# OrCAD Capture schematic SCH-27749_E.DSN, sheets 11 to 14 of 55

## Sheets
11 GVDD & OVDD Power: size C
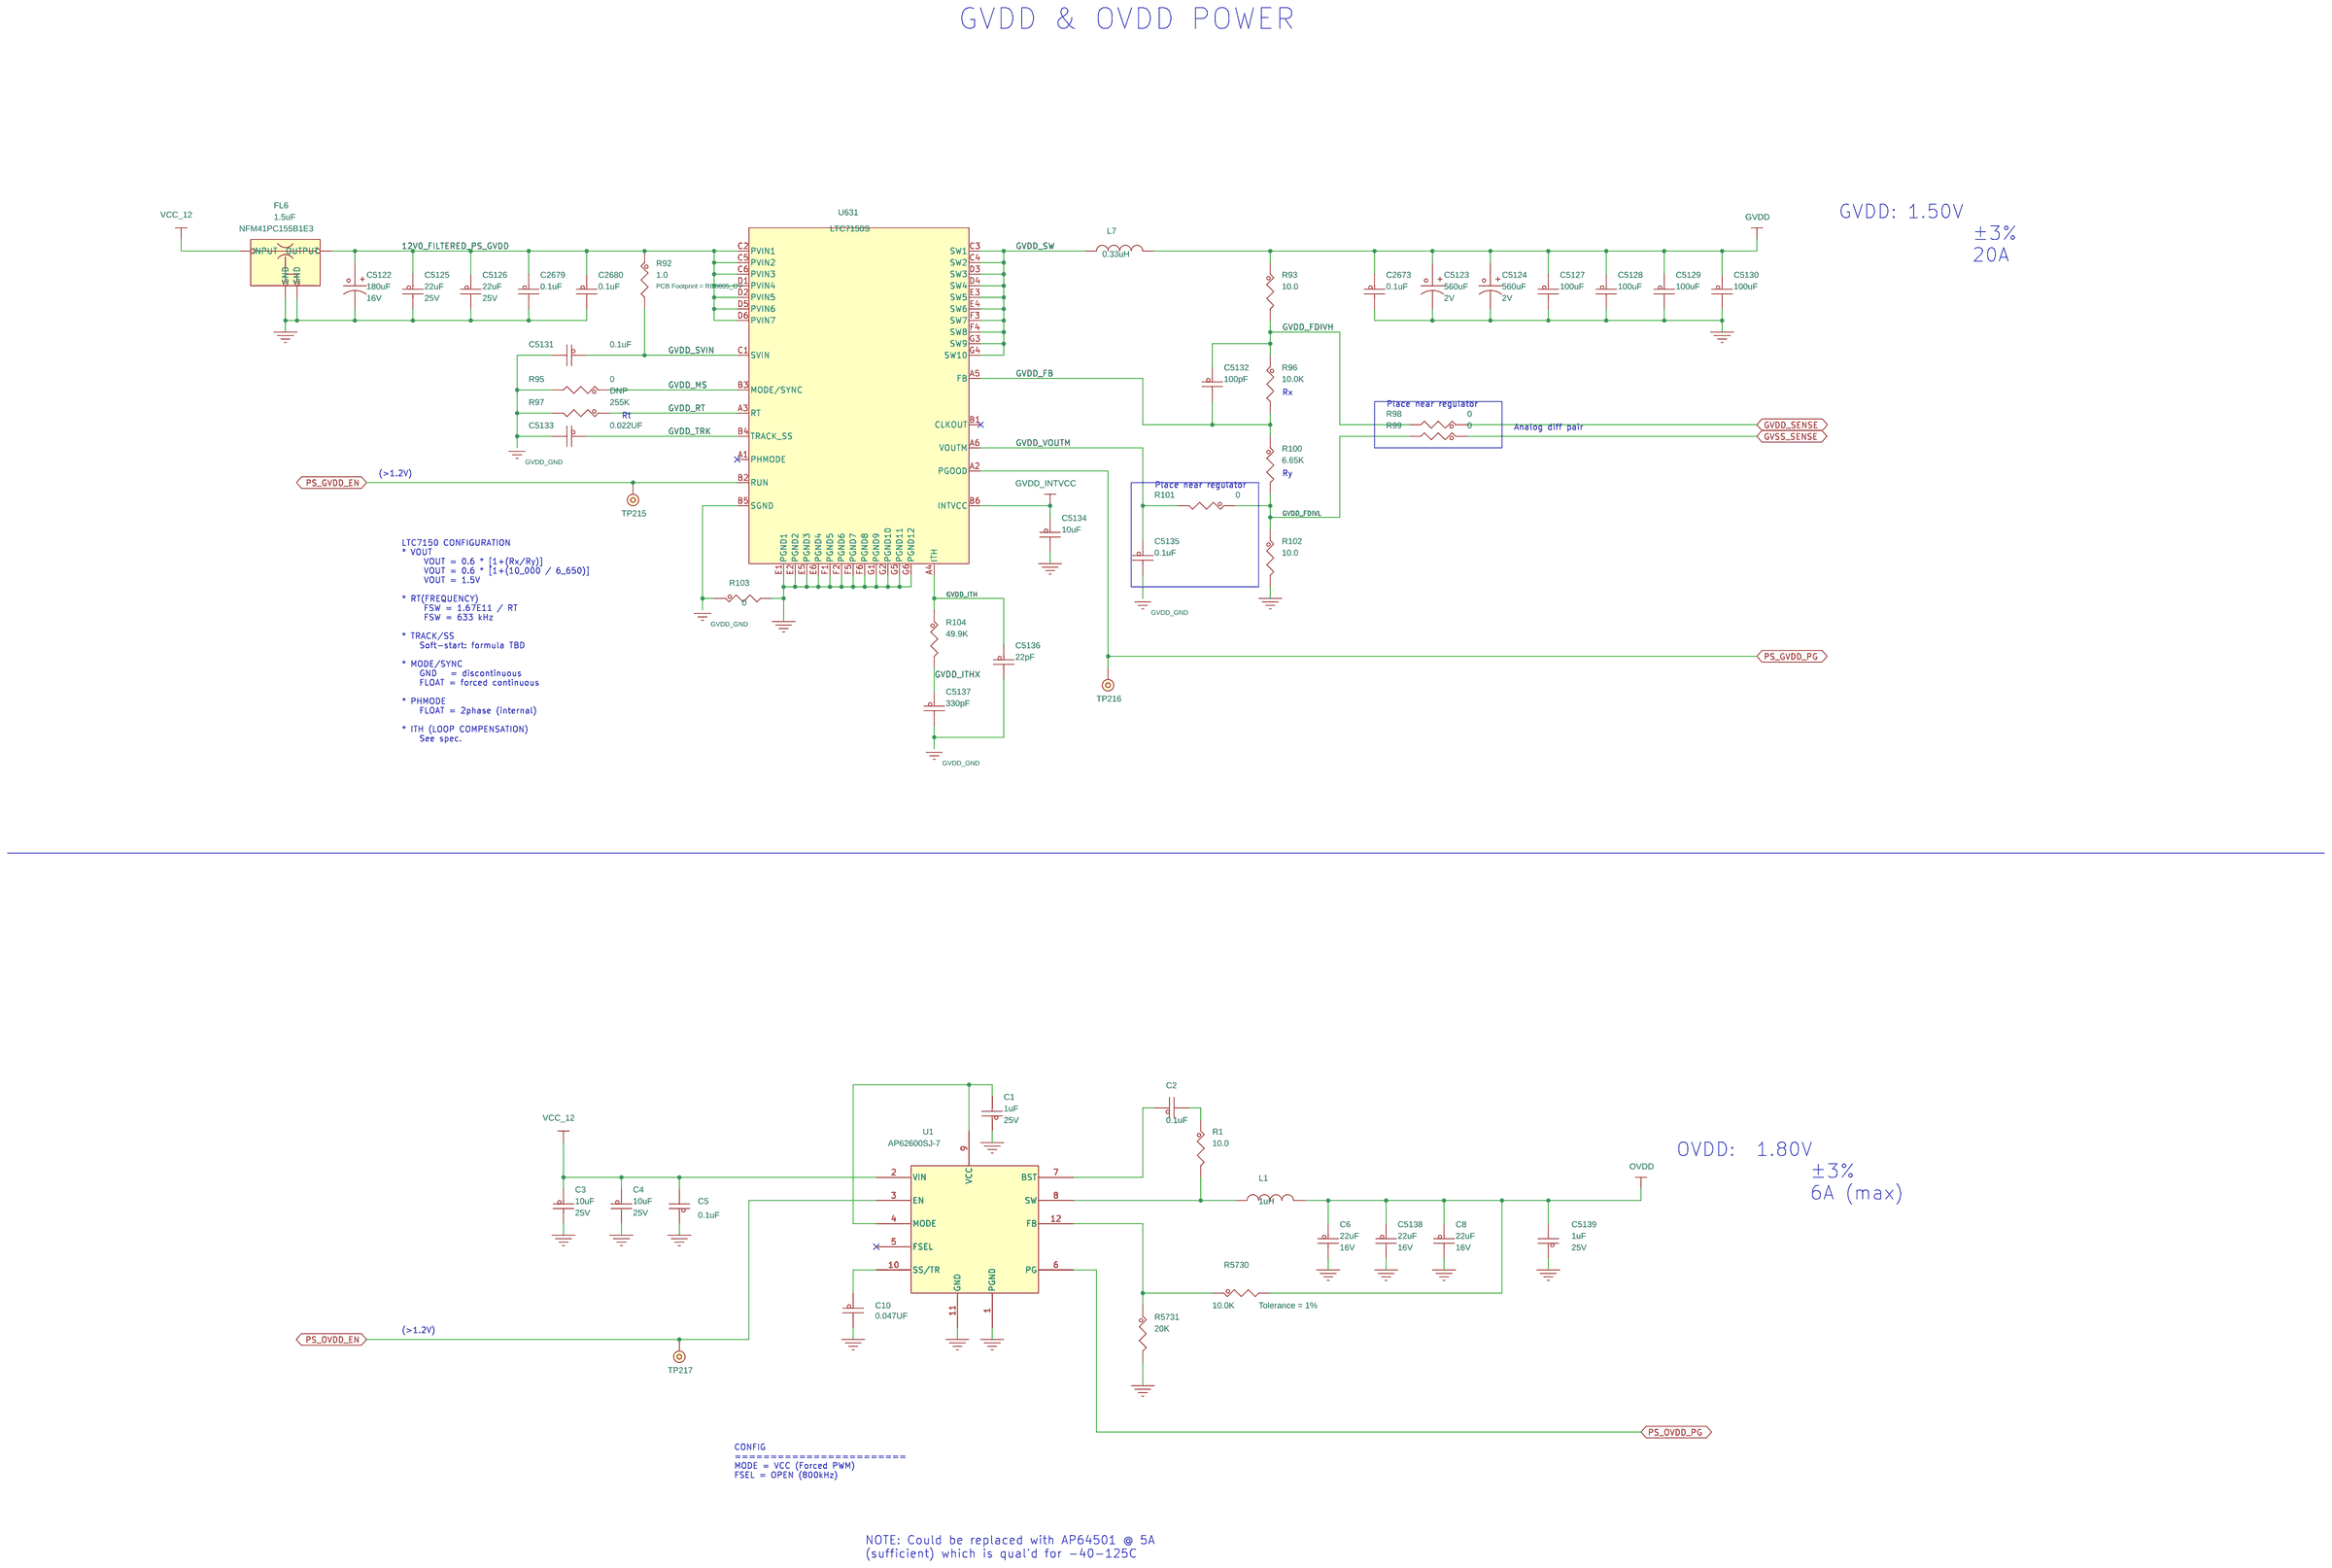
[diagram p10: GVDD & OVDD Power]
12 VDD: size C
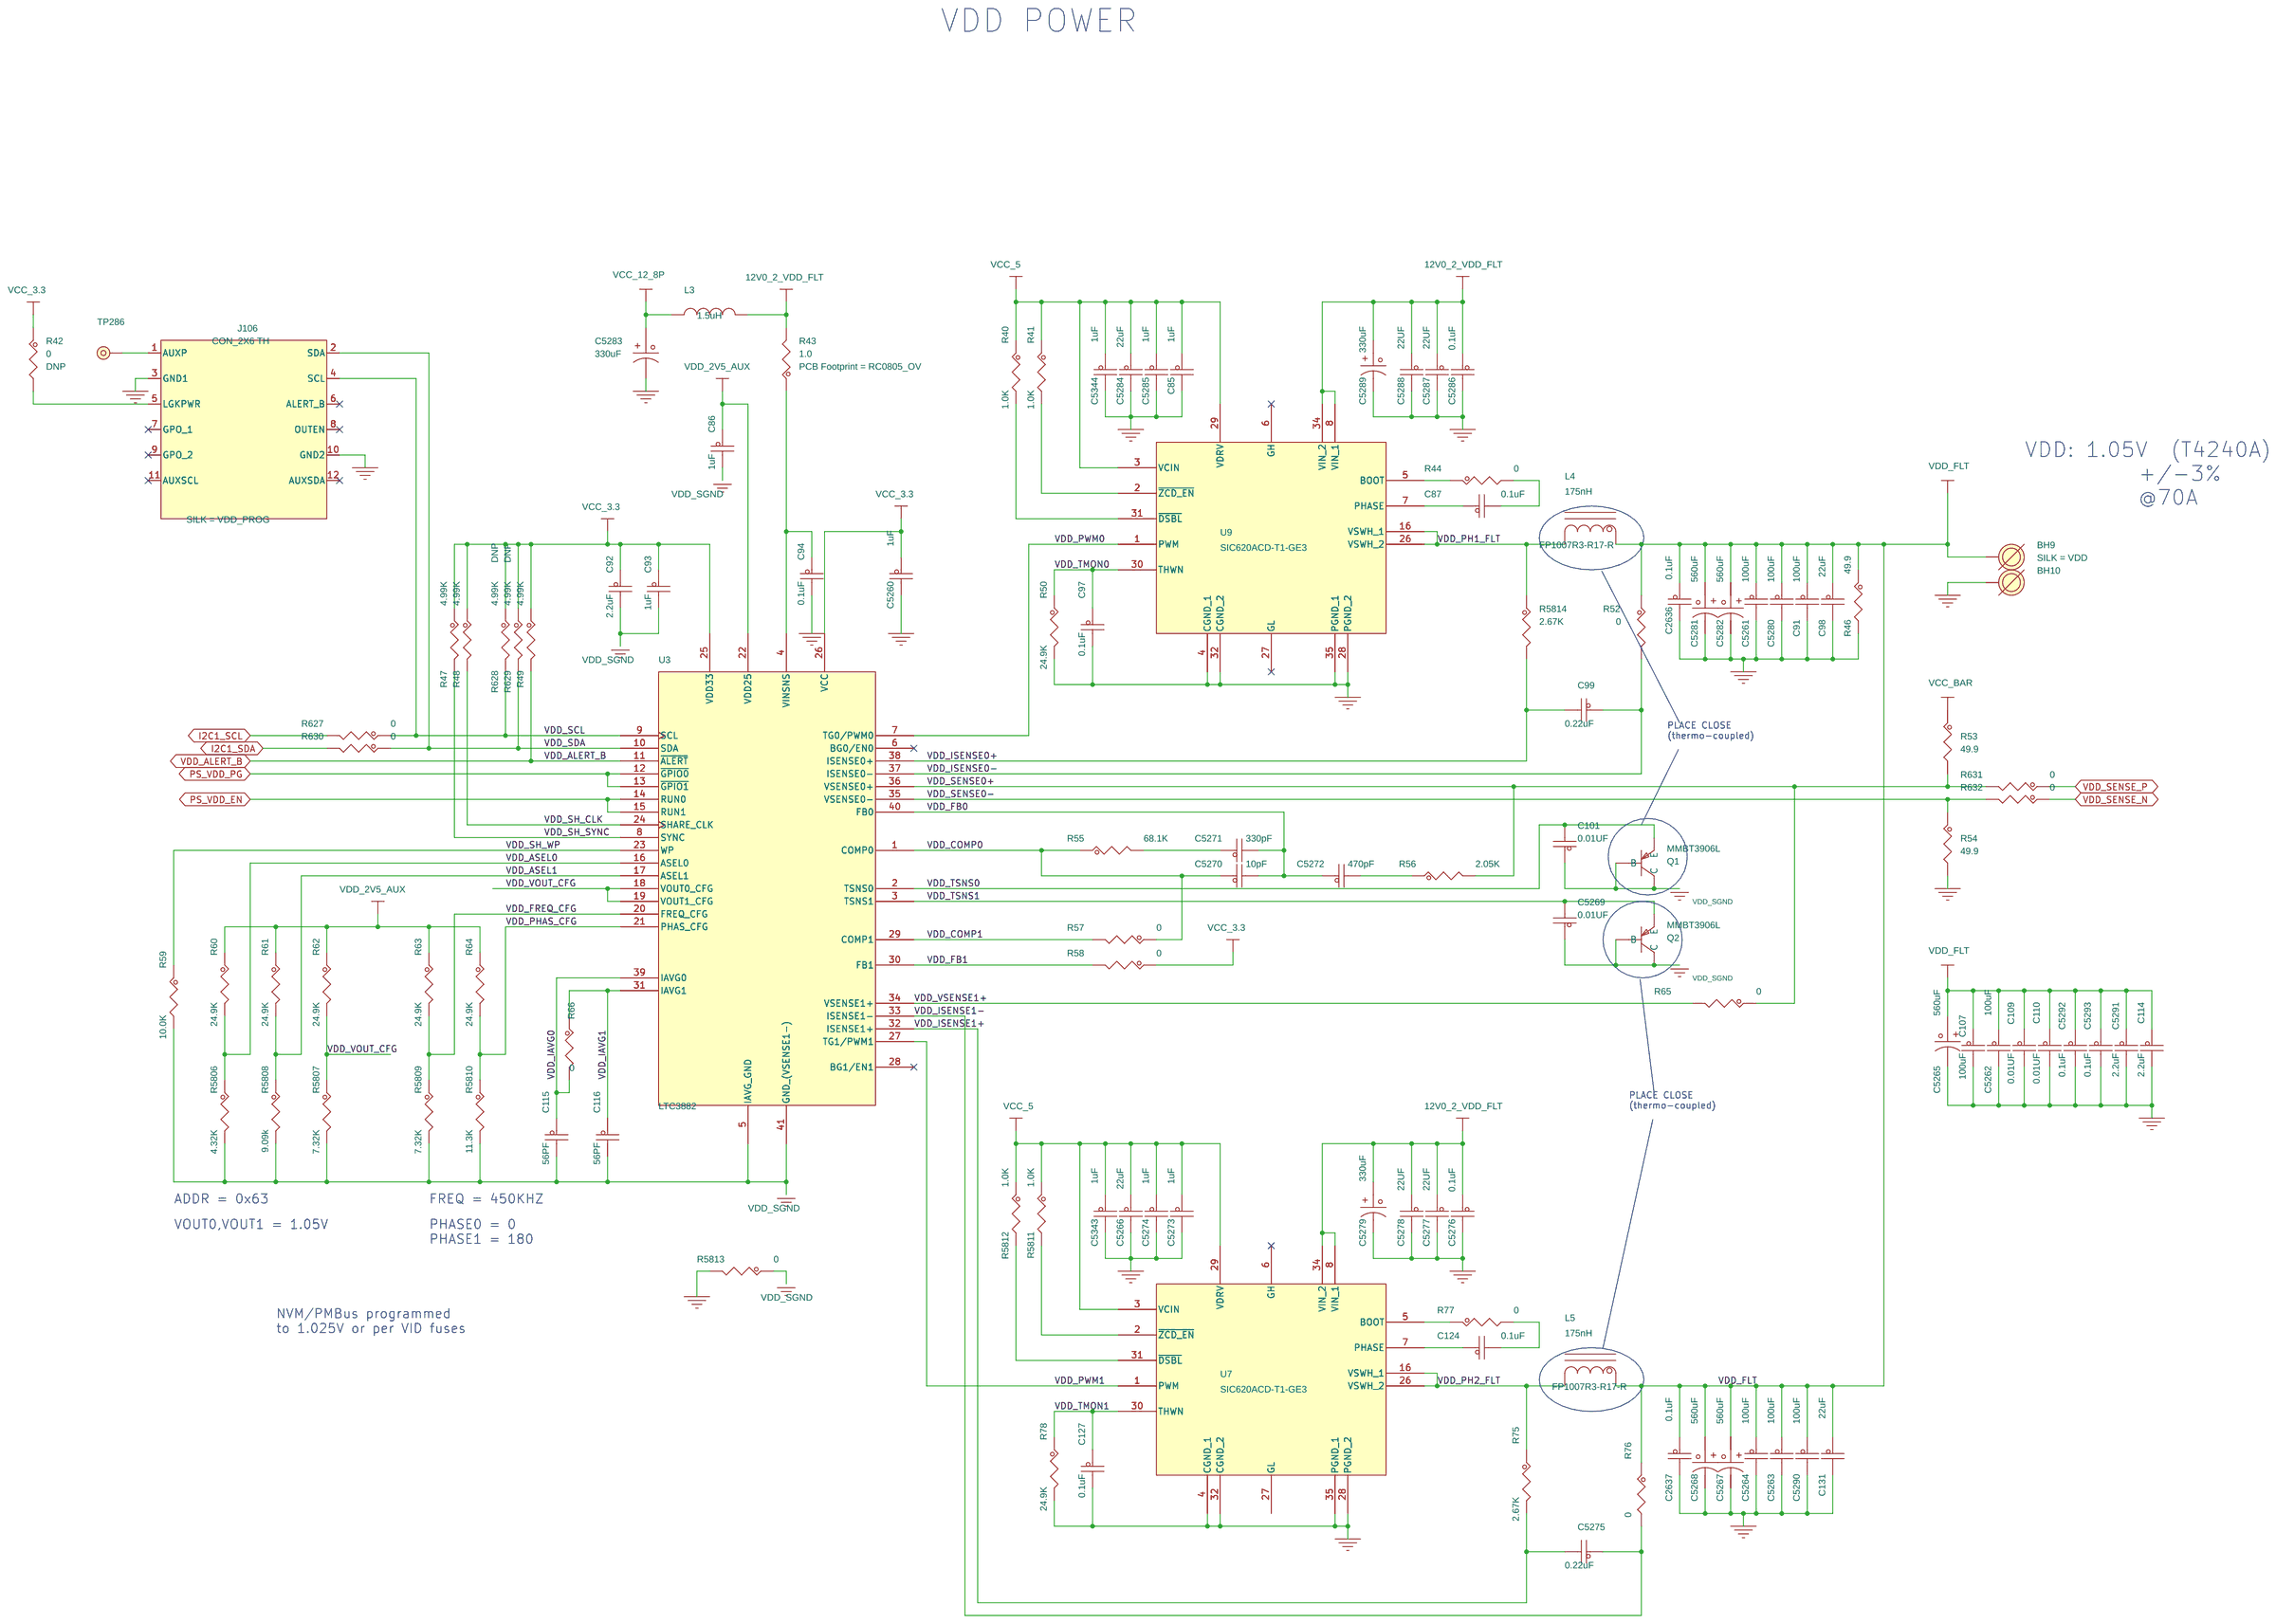
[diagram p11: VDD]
13 DDR MVREF+VTT Power: size C
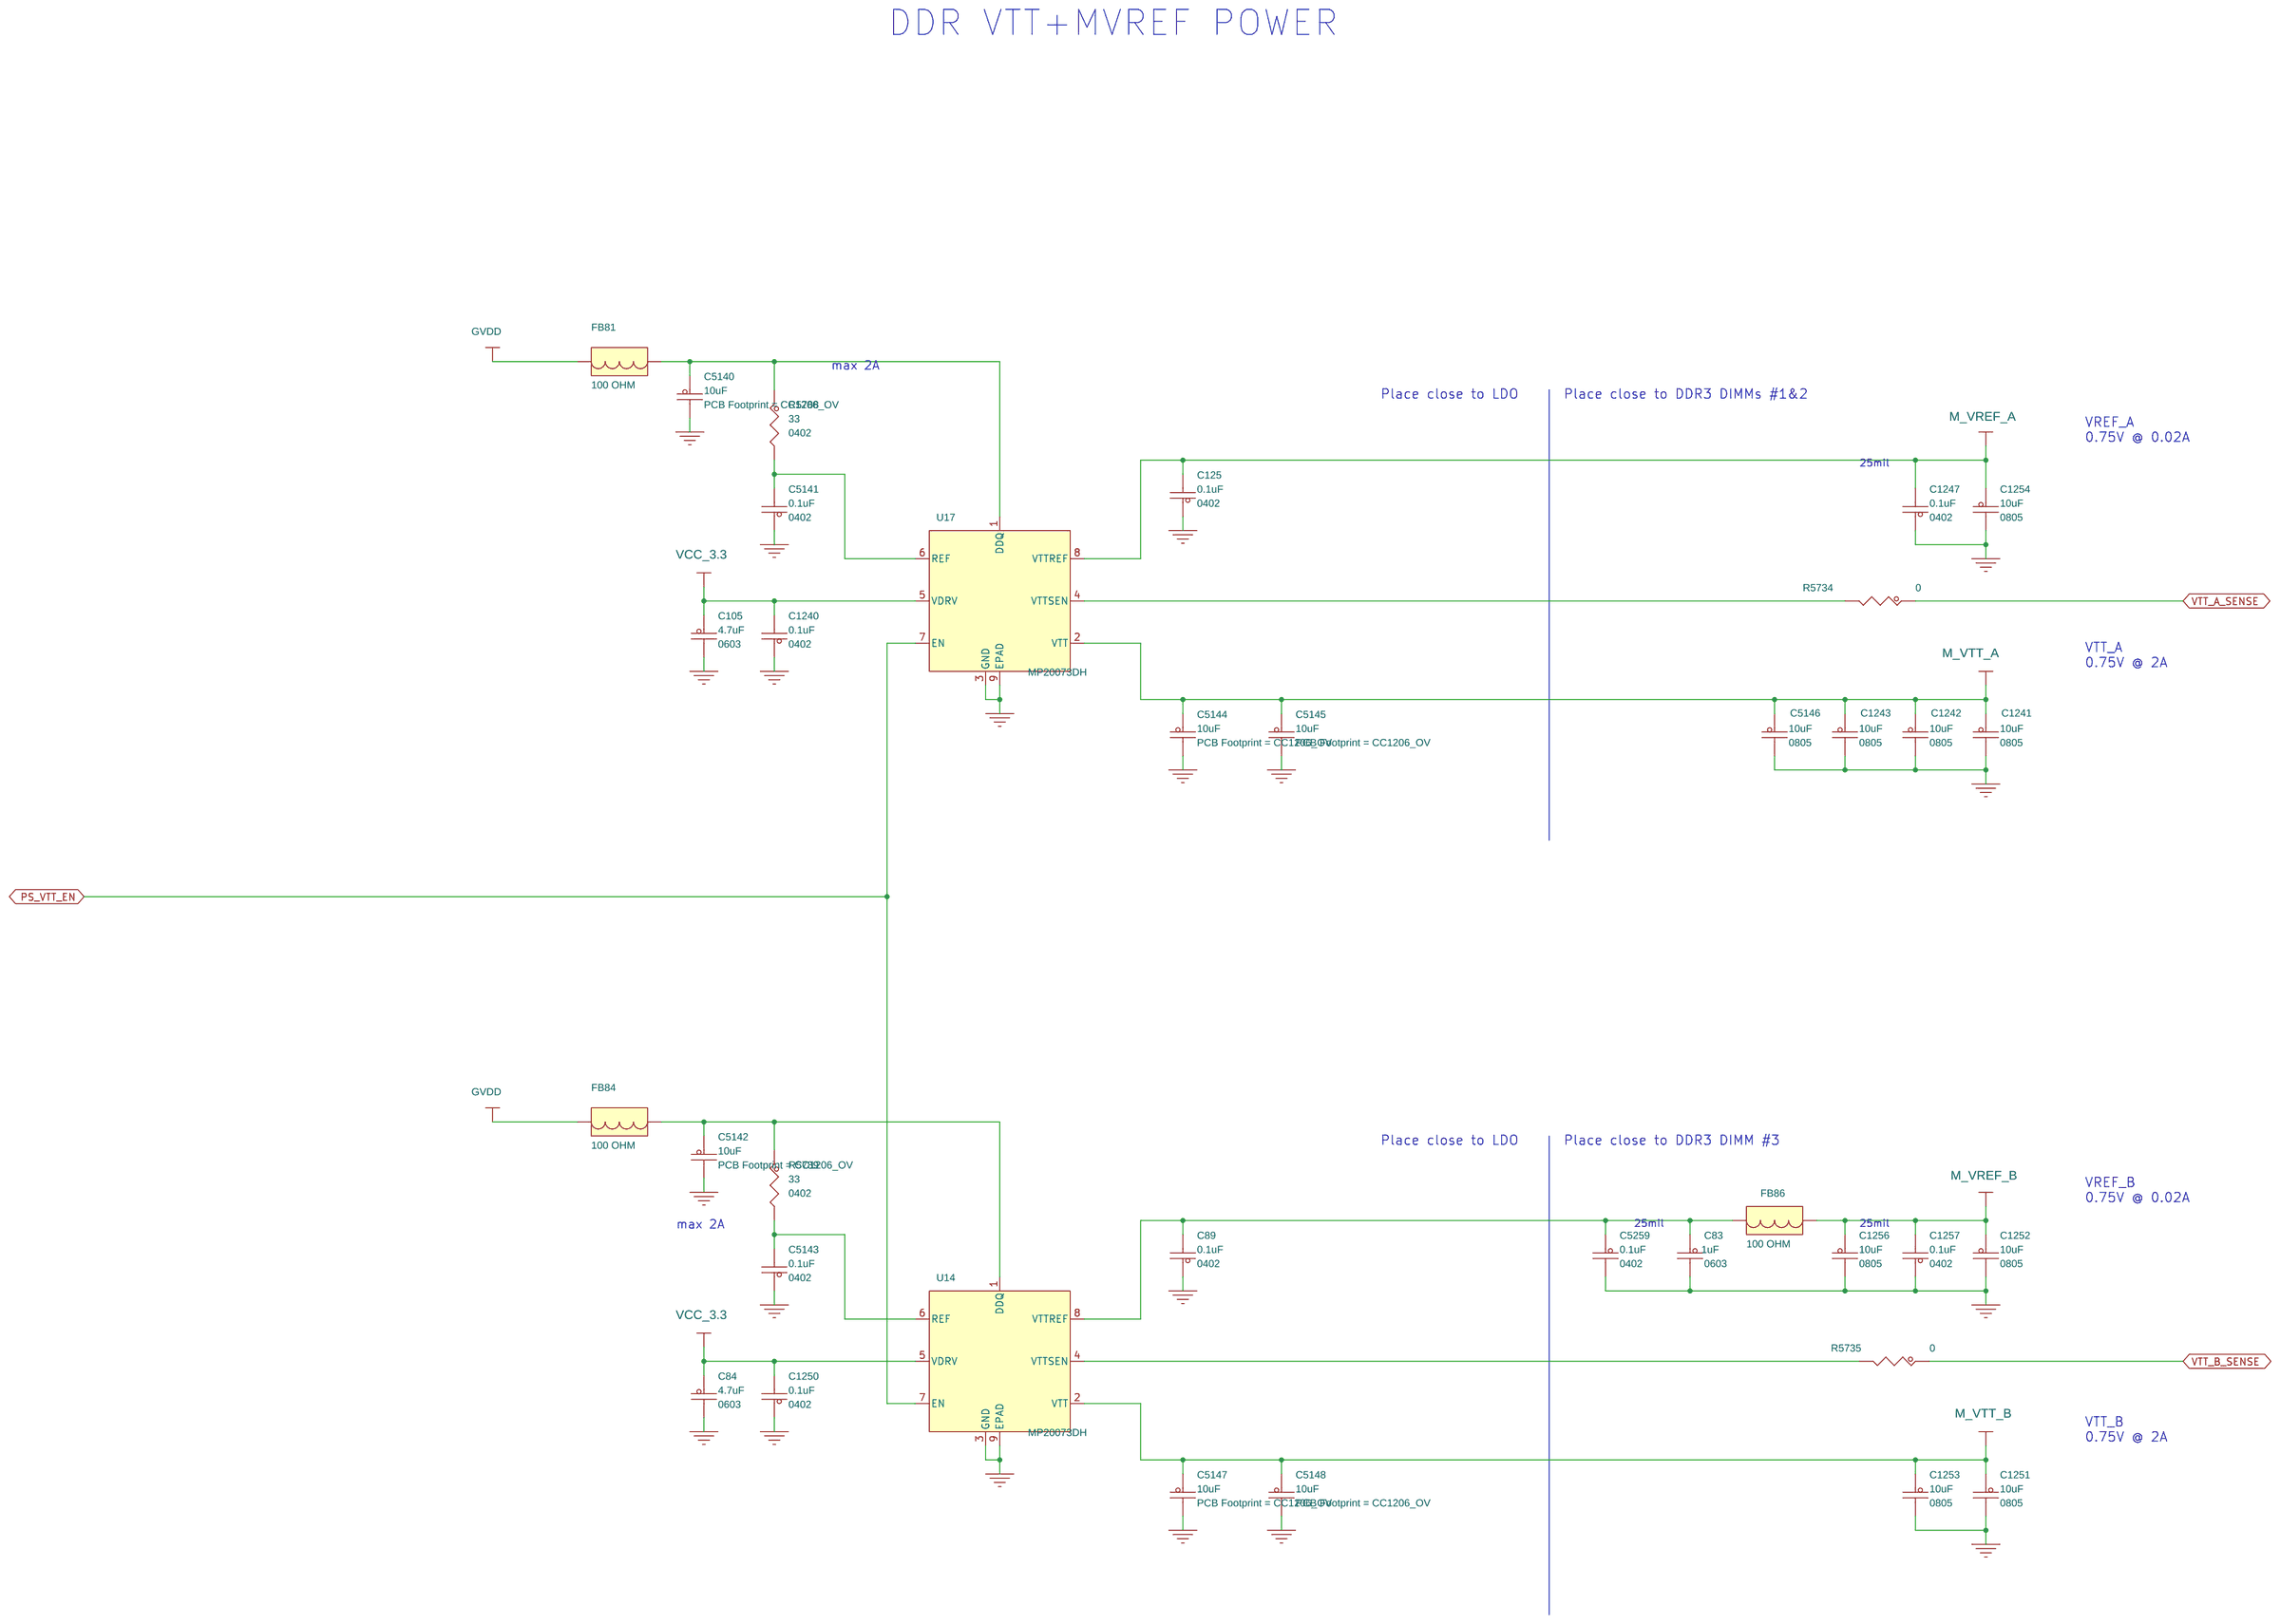
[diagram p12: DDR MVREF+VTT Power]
14 SVDD & XVDD Power: size C
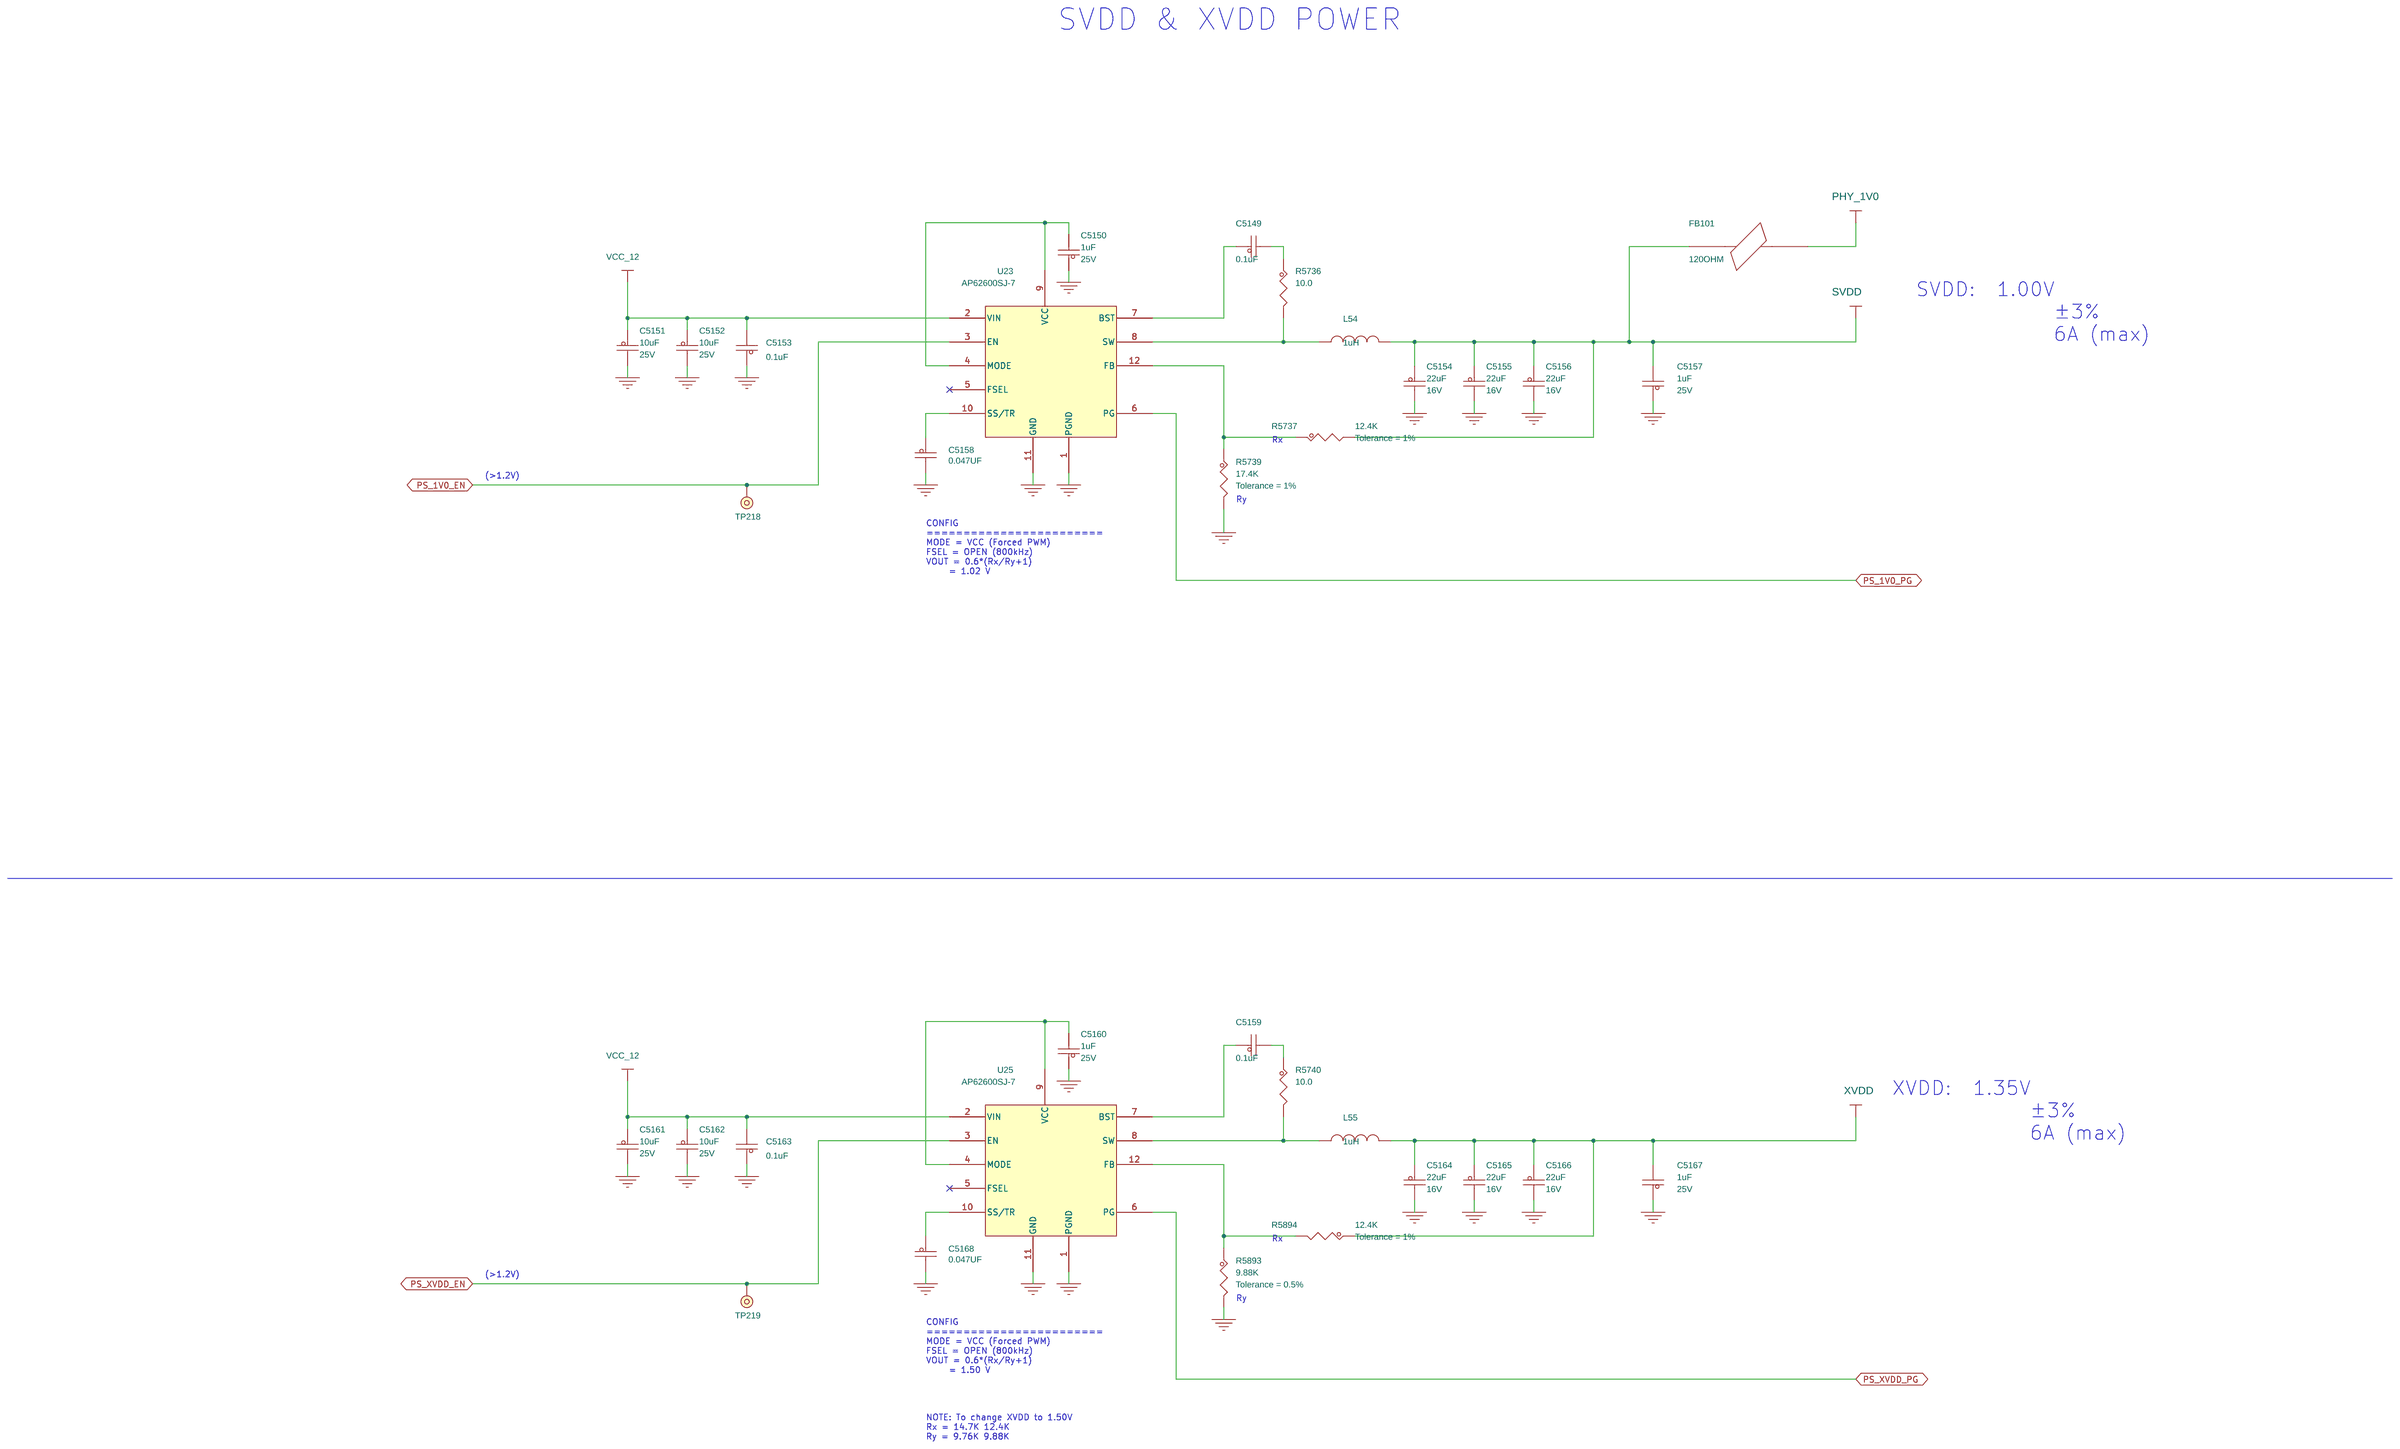
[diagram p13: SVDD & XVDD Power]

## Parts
sheet DDR MVREF+VTT Power
C83  1uF  [CC0603_OV]
C84  4.7uF  [CC0603_OV]
C89  0.1uF  [CC0402_HD]
C105  4.7uF  [CC0603_OV]
C125  0.1uF  [CC0402_HD]
C1240  0.1uF  [CC0402_HD]
C1241  10uF  [CC0603_OV]
C1242  10uF  [CC0603_OV]
C1243  10uF  [CC0603_OV]
C1247  0.1uF  [CC0402_HD]
C1250  0.1uF  [CC0402_HD]
C1251  10uF  [CC0603_OV]
C1252  10uF  [CC0603_OV]
C1253  10uF  [CC0603_OV]
C1254  10uF  [CC0603_OV]
C1256  10uF  [CC0603_OV]
C1257  0.1uF  [CC0402_HD]
C5140  10uF  [CC1206_OV]
C5141  0.1uF  [CC0402_HD]
C5142  10uF  [CC1206_OV]
C5143  0.1uF  [CC0402_HD]
C5144  10uF  [CC1206_OV]
C5145  10uF  [CC1206_OV]
C5146  10uF  [CC0603_OV]
C5147  10uF  [CC1206_OV]
C5148  10uF  [CC1206_OV]
C5259  0.1uF  [CC0402_HD]
FB81  100 OHM  [IND_0805]
FB84  100 OHM  [IND_0805]
FB86  100 OHM  [IND_0805]
R5734  0  [RC0402_25]
R5735  0  [RC0402_25]
R5788  33  [RC0402_25]
R5789  33  [RC0402_25]
U14  MP20073DH  [msop8_0p65_3p1X3p1_EPAD]
U17  MP20073DH  [msop8_0p65_3p1X3p1_EPAD]
sheet GVDD & OVDD Power
C1  1uF  [CC0603_OV]
C2  0.1uF  [CC0402_HD]
C3  10uF  [CC1206_OV]
C4  10uF  [CC1206_OV]
C5  0.1uF  [CC0402_HD]
C6  22uF  [1206_CC]
C8  22uF  [1206_CC]
C10  0.047UF  [CC0603_OV]
C2673  0.1uF  [CC0402_HD]
C2679  0.1uF  [CC0402_HD]
C2680  0.1uF  [CC0402_HD]
C5122  180uF  [cce10_3x10_3]
C5123  560uF  [cc7343a_lp]
C5124  560uF  [cc7343a_lp]
C5125  22uF  [CC0805_OV]
C5126  22uF  [CC0805_OV]
C5127  100uF  [CC1210]
C5128  100uF  [CC1210]
C5129  100uF  [CC1210]
C5130  100uF  [CC1210]
C5131  0.1uF  [CC0402_HD]
C5132  100pF  [CC0402_HD]
C5133  0.022UF  [CC0402_HD]
C5134  10uF  [CC0603_OV]
C5135  0.1uF  [CC0402_HD]
C5136  22pF  [CC0402_HD]
C5137  330pF  [CC0402_HD]
C5138  22uF  [1206_CC]
C5139  1uF  [CC0603_OV]
FL6  1.5uF  [CC_NFM41P_1806]
L1  1uH  [ind2_sq6p9_3_sm]
L7  0.33uH  [ind2_744308033]
R1  10.0  [RC0402_25]
R92  1.0  [RC0805_OV]
R93  10.0  [RC0402_25]
R95  0  [RC0402_25]
R96  10.0K  [RC0402_25]
R97  255K  [RC0402_25]
R98  0  [RC0402_25]
R99  0  [RC0402_25]
R100  6.65K  [RC0402_25]
R101  0  [RC0402_25]
R102  10.0  [RC0402_25]
R103  0  [RC0402_25]
R104  49.9K  [RC0402_25]
R5730  10.0K  [RC0402_25]
R5731  20K  [RC0402_25]
TP215  TPAD_020  [tpad_020_top]
TP216  TPAD_020  [tpad_020_top]
TP217  TPAD_020  [tpad_020_top]
U1  AP62600SJ-7  [qfn12_0p5_2p05x3p05mm]
U631  LTC7150S  [bga42_0p8_5x6]
sheet SVDD & XVDD Power
C5149  0.1uF  [CC0402_HD]
C5150  1uF  [CC0603_OV]
C5151  10uF  [CC1206_OV]
C5152  10uF  [CC1206_OV]
C5153  0.1uF  [CC0402_HD]
C5154  22uF  [1206_CC]
C5155  22uF  [1206_CC]
C5156  22uF  [1206_CC]
C5157  1uF  [CC0603_OV]
C5158  0.047UF  [CC0603_OV]
C5159  0.1uF  [CC0402_HD]
C5160  1uF  [CC0603_OV]
C5161  10uF  [CC1206_OV]
C5162  10uF  [CC1206_OV]
C5163  0.1uF  [CC0402_HD]
C5164  22uF  [1206_CC]
C5165  22uF  [1206_CC]
C5166  22uF  [1206_CC]
C5167  1uF  [CC0603_OV]
C5168  0.047UF  [CC0603_OV]
FB101  120OHM  [IND_0603]
L54  1uH  [ind2_sq6p9_3_sm]
L55  1uH  [ind2_sq6p9_3_sm]
R5736  10.0  [RC0402_25]
R5737  12.4K  [RC0402_25]
R5739  17.4K  [RC0402_25]
R5740  10.0  [RC0402_25]
R5893  9.88K  [RC0402_25]
R5894  12.4K  [RC0402_25]
TP218  TPAD_020  [tpad_020_top]
TP219  TPAD_020  [tpad_020_top]
U23  AP62600SJ-7  [qfn12_0p5_2p05x3p05mm]
U25  AP62600SJ-7  [qfn12_0p5_2p05x3p05mm]
sheet VDD
BH9  MH_180  [MH180-135P]
BH10  MH_180  [MH180-135P]
C85  1uF  [CC0402_HD]
C86  1uF  [CC0402_HD]
C87  0.1uF  [CC0402_HD]
C91  100uF  [CC1210]
C92  2.2uF  [CC0402_HD]
C93  1uF  [CC0402_HD]
C94  0.1uF  [CC0402_HD]
C97  0.1uF  [CC0402_HD]
C98  22uF  [CC0805]
C99  0.22uF  [CC0402_HD]
C101  0.01UF  [CC0402_HD]
C107  100uF  [CC1210]
C109  0.01UF  [CC0402_HD]
C110  0.01UF  [CC0402_HD]
C114  2.2uF  [CC0402_HD]
C115  56PF  [CC0402_HD]
C116  56PF  [CC0402_HD]
C124  0.1uF  [CC0402_HD]
C127  0.1uF  [CC0402_HD]
C131  22uF  [CC0805]
C2636  0.1uF  [CC0402_HD]
C2637  0.1uF  [CC0402_HD]
C5260  1uF  [CC0402_HD]
C5261  100uF  [CC1210]
C5262  100uF  [CC1210]
C5263  100uF  [CC1210]
C5264  100uF  [CC1210]
C5265  560uF  [cc7343a_lp]
C5266  22uF  [CC0805]
C5267  560uF  [cc7343a_lp]
C5268  560uF  [cc7343a_lp]
C5269  0.01UF  [CC0402_HD]
C5270  10pF  [cc0402_hd]
C5271  330pF  [CC0402_HD]
C5272  470pF  [CC0402_25]
C5273  1uF  [CC0402_HD]
C5274  1uF  [CC0402_HD]
C5275  0.22uF  [CC0402_HD]
C5276  0.1uF  [CC0402_HD]
C5277  22UF  [CC1210]
C5278  22UF  [CC1210]
C5279  330uF  [cap_10p5_rad]
C5280  100uF  [CC1210]
C5281  560uF  [cc7343a_lp]
C5282  560uF  [cc7343a_lp]
C5283  330uF  [cap_10p5_rad]
C5284  22uF  [CC0805]
C5285  1uF  [CC0402_HD]
C5286  0.1uF  [CC0402_HD]
C5287  22UF  [CC1210]
C5288  22UF  [CC1210]
C5289  330uF  [cap_10p5_rad]
C5290  100uF  [CC1210]
C5291  2.2uF  [CC0402_HD]
C5292  0.1uF  [CC0402_HD]
C5293  0.1uF  [CC0402_HD]
C5343  1uF  [CC0402_HD]
C5344  1uF  [CC0402_HD]
J106  CON_2X6 TH  [CON12_SHRD_2MM_TH]
L3  1.5uH  [IND_IHLP]
L4  175nH  [IND2_10P4X8]
L5  175nH  [IND2_10P4X8]
Q1  MMBT3906L  [SOT23]
Q2  MMBT3906L  [SOT23]
R40  1.0K  [RC0402_HD]
R41  1.0K  [RC0402_HD]
R42  0  [RC0603_OV]
R43  1.0  [RC0805_OV]
R44  0  [RC0402_25]
R46  49.9  [RC0402_25]
R47  4.99K  [RC0402_25]
R48  4.99K  [RC0402_25]
R49  4.99K  [RC0402_25]
R50  24.9K  [RC0402_25]
R52  0  [RC0402_25]
R53  49.9  [RC0402_25]
R54  49.9  [RC0402_25]
R55  68.1K  [RC0402_25]
R56  2.05K  [RC0402_25]
R57  0  [RC0402_25]
R58  0  [RC0402_25]
R59  10.0K  [RC0402_25]
R60  24.9K  [RC0402_25]
R61  24.9K  [RC0402_25]
R62  24.9K  [RC0402_25]
R63  24.9K  [RC0402_25]
R64  24.9K  [RC0402_25]
R65  0  [RC0402_25]
R66  0  [RC0402_25]
R75  2.67K  [RC0402_25]
R76  0  [RC0402_25]
R77  0  [RC0402_25]
R78  24.9K  [RC0402_25]
R627  0  [RC0402_25]
R628  4.99K  [RC0402_25]
R629  4.99K  [RC0402_25]
R630  0  [RC0402_25]
R631  0  [RC0402_25]
R632  0  [RC0402_25]
R5806  4.32K  [RC0402_25]
R5807  7.32K  [RC0402_25]
R5808  9.09k  [RC0402_25]
R5809  7.32K  [RC0402_25]
R5810  11.3K  [RC0402_25]
R5811  1.0K  [RC0402_HD]
R5812  1.0K  [RC0402_HD]
R5813  0  [RC0603_OV]
R5814  2.67K  [RC0402_25]
TP286  TPAD_020  [tpad_020_top]
U3  LTC3882  [QFN40_0P5_6P1X6P1]
U7  SIC620ACD-T1-GE3  [powerpak_mlp55]
U9  SIC620ACD-T1-GE3  [powerpak_mlp55]

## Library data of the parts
C83 = CAP_NP: CAP CER 1UF 25V 10% X7R 0603; AGILE_PN: 150-30185; CAD_APPROVED: Yes; FPLIST: CC0603_OV,CC0603,0603_CC; HEIGHT: 0.9mm; MFG_NAME01: WURTH ELEKTRONIK EISOS GMBH & CO. KG (ELECTRONIC & ELECTROMEHANICAL COMP); MFG_PN01: 885012206076; Package: 0603; Package Size: 0603; Package Type: tape & reel; Part Number: 4CC105C251X00; Product Name: (H)MLCC 1uF/25V +-10% 0603 X5R; ROHS: Yes; Rated Voltage: 25V; Temp Range: -55C to +125C; Tolerance: 10%
C84 C105 = CAP_NP: CAP CER 4.7uF 10V 10% X5R 0603; AGILE_PN: 150-79199; CAD_APPROVED: Yes; FPLIST: CC0603_OV,CC0603,0603_CC; HEIGHT: 0.9MM; MFG_NAME01: TDK; MFG_PN01: C1608X5R1A475K080AC; Package: 0603; Package Size: 0603; Part Number: 4CC475C101X00; Product Name: (N)(H)MLCC 4.7uF/10V +-10% 0603 X5R; ROHS: Yes; Rated Voltage: 10V; Temp Range: -55C to +85C; Tolerance: 10%
C89 C125 C1240 C1247 C1250 C1257 C5141 C5143 C5259 = CAP_NP: CAP CER 0.1uF 16V 10% X7R AEC-Q200 0402; AGILE_PN: 150-79025; CAD_APPROVED: Yes; FPLIST: CC0402_25,CC0402_HD,0402_CC,capc0402_l; HEIGHT: 0.55MM; MFG_NAME01: MURATA; MFG_PN01: GCM155R71C104KA55D; Package: 0402; Package Size: 0402; Package Type: ø180mm Reel PAPER; Part Number: 4CC104B163X00; Product Name: (H)MLCC 0.1uF/16V +-10% 0402 X7R; ROHS: Yes; Rated Voltage: 16V; Temp Range: -55C to +125C; Tolerance: 10%
C1241-C1243 C1251-C1254 C1256 C5146 = CAP_NP: CAP CER 10UF 10V 10% X5R 0603; AGILE_PN: 150-78675; CAD_APPROVED: Yes; FPLIST: CC0603_OV,CC0603,0603_CC_NSP; HEIGHT: 1.016MM; MFG_NAME01: MURATA; MFG_PN01: GRM188R61A106KE69D; Package: 0805; Part Number: 4CC106D101X00; Product Name: (H)MLCC 10uF/10V +/-10% 0805 X5R; ROHS: Yes; Rated Voltage: 10V; Temp Range: -55C to +85C; Tolerance: 10%
C3 C4 C5140 C5142 C5144 C5145 C5147 C5148 C5151 C5152 C5161 C5162 = CAP_NP: CAP CER 10uF 25V 10% X7R 1206; AGILE_PN: 150-79147; CAD_APPROVED: Yes; FPLIST: CC1206_OV,CC1206,1206_CC; HEIGHT: 1.8MM; MFG_NAME01: MURATA; MFG_PN01: GRM31CR71E106KA12; ROHS: Yes; Rated Voltage: 25V; Temp Range: -55C to +125C; Tolerance: 10%
FB81 FB84 FB86 = BEAD: IND FER BEAD 100OHM@100MHZ 4A 25% AEC-Q200 0805; AGILE_PN: 180-78923; CAD_APPROVED: Yes; HEIGHT: 1.05MM; MFG_NAME01: TDK; MFG_PN01: MPZ2012S101ATD25; Package Size: 2x1.25MM; ROHS: Yes; Temp Range: -55°C to +125°C
R44 R52 R57 R58 R65 R66 R76 R77 R101 R627 R630-R632 R5734 R5735 = RES: RES MF ZERO OHM 1/10W -- 0402; AGILE_PN: 470-79965; CAD_APPROVED: Yes; FPLIST: RC0402_25,RC0402_HD,RC0402_X2,0402_CC; HEIGHT: 0.4MM; MFG_NAME01: PANASONIC; MFG_PN01: ERJ-2GE0R00X; ROHS: Yes; ROOM: VDD_GVDD_PS; SIGNAL_MODEL: RES_RC0402_25_DISCRETE_0.35MM_4_0; TOL: 5%; Temp Range: –55 °C to +155 °C; VOLTAGE: 1/10W
R5788 R5789 = RES: RES MF 33 OHM 1/10W 5% AEC-Q200 0402; AGILE_PN: 470-82134; CAD_APPROVED: Yes; FPLIST: RC0402_25,RC0402_HD,0402_CC; HEIGHT: 0.4MM; MFG_NAME01: KOA SPEER; MFG_PN01: RK73B1ETTP330J; Package: 0402; Part Number: 4RC3300B11X00; Product Name: (H)RES 33E 1/16W 0402 1% PBFREE; ROHS: Yes; Temp Range: -55&#8451; to 155&#8451;; Tolerance: 5%
U14 U17 = MP20073DH_8P_EP: IC VREG DDR TERM 1.3-6V 2A MSOP8E; 3D_Mechanical_Footprint_File: http://fcl.am.freescale.net/ALLEGRO/step/msop8_0p65_3p1x3p1_epad.STEP; AGILE_PN: 315-80289; CAD_APPROVED: Yes; HEIGHT: 1.1MM; MFG_NAME01: MONOLITHIC POWER SYSTEMS; ROHS: Yes; VOLTAGE: 1.3-6V
C1 C5139 C5150 C5157 C5160 C5167 = CAP_NP: CAP CER 1UF 25V 10% X7R 0603; AGILE_PN: 150-30185; CAD_APPROVED: Yes; FPLIST: CC0603_OV,CC0603,0603_CC; HEIGHT: 0.9mm; MFG_NAME01: WURTH ELEKTRONIK EISOS GMBH & CO. KG (ELECTRONIC & ELECTROMEHANICAL COMP); MFG_PN01: 885012206076; Package Size: 0603; Package Type: tape & reel; ROHS: Yes; Rated Voltage: 25V; Temp Range: -55C to +125C; Tolerance: 10%
C2 C5 C5149 C5153 C5159 C5163 = CAP_NP: CAP CER 0.1uF 16V 10% X7R AEC-Q200 0402; AGILE_PN: 150-79025; CAD_APPROVED: Yes; FPLIST: CC0402_25,CC0402_HD,0402_CC,capc0402_l; HEIGHT: 0.55MM; MFG_NAME01: MURATA; MFG_PN01: GCM155R71C104KA55D; Package Size: 0402; Package Type: ø180mm Reel PAPER; ROHS: Yes; Rated Voltage: 16V; Temp Range: -55C to +125C; Tolerance: 10%
C6 C8 C5138 C5154-C5156 C5164-C5166 = CAP_NP: CAP CER 22uF 16V 20% X6S AEC-Q200 1206; AGILE_PN: 150-81260; CAD_APPROVED: Yes; HEIGHT: 1.8 mm; MFG_NAME01: Murata Electronics; MFG_PN01: GRT31CC81C226ME01L; Package Size: 1206 (3216 metric); Package Type: SMD/SMT; ROHS: Yes; Rated Voltage: 16V; Temp Range: -55C to +105C; Tolerance: 20%
C10 C5158 C5168 = CAP_NP: CAP CER 0.047UF 25V 10% X7R 0603; AGILE_PN: 150-75199; CAD_APPROVED: Yes; FPLIST: CC0603_OV,CC0603,0603_CC; HEIGHT: 0.9652mm; MFG_NAME01: VENKEL COMPANY; MFG_PN01: C0603X7R250-473KNE; Package Size: 0603; Package Type: embossed tape; ROHS: Yes; Rated Voltage: 25V; Temp Range: -55C to +125C; Tolerance: 10%
C2673 C2679 C2680 C5131 = CAP_NP: CAP CER 0.1uF 16V 10% X7R AEC-Q200 0402; AGILE_PN: 150-79025; CAD_APPROVED: Yes; FPLIST: CC0402_25,CC0402_HD,0402_CC,capc0402_l; HEIGHT: 0.55MM; MFG_NAME01: MURATA; MFG_PN01: GCM155R71C104KA55D; Package Size: 0402; Package Type: ø180mm Reel PAPER; ROHS: Yes; Rated Voltage: 16V; Temp Range: -55C to +125C; Tolerance: 10%; VOLTAGE: 35V
C5122 = CAP_POL: CAP ALEL ESR 0.030OHM 180UF 16V 20% SMT; 3D_Mechanical_Footprint_File: http://fcl.am.freescale.net/ALLEGRO/step/cce10_3x10_3_315h.STEP; AGILE_PN: 150-78891; CAD_APPROVED: Yes; HEIGHT: 8MM; MFG_NAME01: SANYO; MFG_PN01: 16SVP180MX; Package Size: F8; ROHS: Yes; Rated Voltage: 16V; Tolerance: 20%; VOLTAGE: 16V
C5123 C5124 C5265 C5267 C5268 C5281 C5282 = CAP_POL: CAP POLYMER-EL 560uF 20% 7343; 3D_Mechanical_Footprint_File: http://fcl.am.freescale.net/ALLEGRO/step/CC7343A_LP.step; AGILE_PN: 150-79314; CAD_APPROVED: Yes; HEIGHT: 2.1MM; MFG_NAME01: PANASONIC; MFG_PN01: EEFGX0D561R; Package Size: 7343; ROHS: Yes; ROOM: VDD_GVDD_PS; Rated Voltage: 2V; Temp Range: -55C to +105C; Tolerance: 20%; VOLTAGE: 2V
C5125 C5126 = CAP_NP: CAP CER 22uF 25V 20% X5R 0805; AGILE_PN: 150-79304; CAD_APPROVED: Yes; FPLIST: CC0805_OV,CC0805,0805_CC; HEIGHT: 1.45MM; MFG_NAME01: MURATA; MFG_PN01: GRM21BR61E226ME44; Package Size: 0805; Package Type: SMD; ROHS: Yes; Rated Voltage: 25V; SIGNAL_MODEL: DEFAULT_CAPACITOR_2.2e+07pF_2_1; Temp Range: -55C to +85C; Tolerance: 20%; VOLTAGE: 25V
C5127-C5130 = CAP_NP: CAP CER 100uF 10V 20% X5R 1210; AGILE_PN: 150-78879; CAD_APPROVED: Yes; FPLIST: CC1210,1210_CC; HEIGHT: 2.8MM; MFG_NAME01: MURATA; MFG_PN01: GRM32ER61A107ME20L; Package Size: 1210; Package Type: 7" Tape; ROHS: Yes; ROOM: VDD_GVDD_PS; Rated Voltage: 10V; Temp Range: -55C to +85C; Tolerance: 20%; VOLTAGE: 6.3V
C5132 = CAP_NP: CAP CER 100PF 50V 5% X7R 0402; AGILE_PN: 150-78133; CAD_APPROVED: Yes; FPLIST: CC0402_25,CC0402_HD,0402_CC,capc0402_l; HEIGHT: 0.6MM; MFG_NAME01: CAL-CHIP; MFG_PN01: GMC04X7R101J50NT-LF; Package Size: 0402; ROHS: Yes; Rated Voltage: 50V; TOL: 5%; Temp Range: -55C to +125C; Tolerance: 5%
C5133 = CAP_NP: CAP CER 0.022UF 16V 10% X7R 0402; AGILE_PN: 150-30293; CAD_APPROVED: Yes; FPLIST: CC0402_25,CC0402_HD,0402_CC,capc0402_l; HEIGHT: 0.56MM; MFG_NAME01: AVX; MFG_PN01: 0402YC223KAT2A; ROHS: Yes; Rated Voltage: 16V; Temp Range: -55C to +125C; Tolerance: 10%; VOLTAGE: 16V
C5134 = CAP_NP: CAP CER 10UF 10V 10% X5R 0603; AGILE_PN: 150-78675; CAD_APPROVED: Yes; FPLIST: CC0603_OV,CC0603,0603_CC_NSP; HEIGHT: 1.016MM; MFG_NAME01: MURATA; MFG_PN01: GRM188R61A106KE69D; ROHS: Yes; Rated Voltage: 10V; Temp Range: -55C to +85C; Tolerance: 10%; VOLTAGE: 6.3V
C5135 = CAP_NP: CAP CER 0.1uF 16V 10% X7R AEC-Q200 0402; AGILE_PN: 150-79025; CAD_APPROVED: Yes; FPLIST: CC0402_25,CC0402_HD,0402_CC,capc0402_l; HEIGHT: 0.55MM; MFG_NAME01: MURATA; MFG_PN01: GCM155R71C104KA55D; Package Size: 0402; Package Type: ø180mm Reel PAPER; ROHS: Yes; Rated Voltage: 16V; SIGNAL_MODEL: DEFAULT_CAPACITOR_100000pF_2_1; TOL: 10%; Temp Range: -55C to +125C; Tolerance: 10%; VOLTAGE: 6.3V
C5136 = CAP_NP: CAP CER 22pF 50V 5% C0G AEC-Q200 0402; AGILE_PN: 150-79024; CAD_APPROVED: Yes; FPLIST: CC0402_25,CC0402_HD,0402_CC,capc0402_l; HEIGHT: 0.55MM; MFG_NAME01: MURATA; MFG_PN01: GCM1555C1H220JA16J; Package Size: 0402; ROHS: Yes; Rated Voltage: 50V; Temp Range: -55C to +125C; Tolerance: 5%; VOLTAGE: 50V
C5137 C5271 = CAP_NP: CAP CER 330pF 50V 5% C0G AEC-Q200 0402; AGILE_PN: 150-79035; CAD_APPROVED: Yes; FPLIST: CC0402_25,CC0402_HD,0402_CC,capc0402_l; HEIGHT: 0.55MM; MFG_NAME01: MURATA; MFG_PN01: GCM1555C1H331JA16D; Package Size: 0402; Package Type: Paper Tape; ROHS: Yes; Rated Voltage: 50V; Temp Range: -55C to +125C; Tolerance: 5%; VOLTAGE: 50V
FL6 = EMIFILTER_CC: CAP FILTER EMI 1.5uF 25V 20% -- 1806; 3D_Mechanical_Footprint_File: http://fcl.am.freescale.net/ALLEGRO/step/CC_NFM41P_1806.STEP; AGILE_PN: 150-79370; CAD_APPROVED: Yes; HEIGHT: 1.2 MM; MFG_NAME01: MURATA; MFG_PN01: NFM41PC155B1E3; ROHS: Yes; Rated Voltage: 25V; Temp Range: -55C to +85C; Tolerance: 20%; VOLTAGE: 25V
L1 L54 L55 = INDUCTOR: IND PWR 1uH@100kHz 11A 20% AEC-Q200 SMD; 3D_Mechanical_Footprint_File: http://fcl.am.freescale.net/ALLEGRO/step/ind2_sq6p9_3_sm.step; AGILE_PN: 180-81433; CAD_APPROVED: Yes; HEIGHT: 3.00MM; MFG_NAME01: Pulse Electronics; MFG_PN01: PA4341.102NLT; Package Size: 7.6 x 6.9 mm; ROHS: Yes; Temp Range: -55C to +125C
L7 = INDUCTOR: IND PWR 0.33uH@100KHZ 27A 20% SMD; 3D_Mechanical_Footprint_File: http://fcl.am.freescale.net/ALLEGRO/step/ind2_744308033.step; AGILE_PN: 180-77944; CAD_APPROVED: Yes; HEIGHT: 7MM; MFG_NAME01: WURTH ELEKTRONIK EISOS GMBH & CO. KG (ELECTRONIC & ELECTROMEHANICAL COMP); MFG_PN01: 744308033; PART_TYPE: INDUCTOR\POWER; ROHS: Yes; Tolerance: 20%
R1 R93 R102 R5736 R5740 = RES: RES MF 10.0 OHM 1/16W 1% 0402; 3D_Mechanical_Footprint_File: http://fcl.am.freescale.net/ALLEGRO/step/rc0402_25.STEP; AGILE_PN: 470-76090; CAD_APPROVED: Yes; FPLIST: RC0402_25,RC0402_HD,0402_CC; HEIGHT: 0.4MM; MFG_NAME01: BOURNS; MFG_PN01: CR0402-FX-10R0GLF; ROHS: Yes; Tolerance: 1%
R43 R92 = RES: RES MF 1.0 OHM 1/8W 1% 0805; AGILE_PN: 470-76317; CAD_APPROVED: Yes; FPLIST: RC0805_OV,RC0805,0805_CC; HEIGHT: 0.6MM; MFG_NAME01: YAGEO AMERICA; MFG_PN01: RC0805FR-071RL; ROHS: Yes; ROOM: VDD_GVDD_PS; SIGNAL_MODEL: DEFAULT_RESISTOR_1OHM_2_1; Tolerance: 1%; VOLTAGE: 1/8W
R95 = RES: RES MF ZERO OHM 1/10W -- 0402; AGILE_PN: 470-79965; ASSY_OPT: DNP; CAD_APPROVED: Yes; FPLIST: RC0402_25,RC0402_HD,RC0402_X2,0402_CC; HEIGHT: 0.4MM; MFG_NAME01: PANASONIC; MFG_PN01: ERJ-2GE0R00X; ROHS: Yes; ROOM: VDD_GVDD_PS; TOL: 5%; Temp Range: –55 °C to +155 °C; VOLTAGE: 1/10W
R96 R5730 = RES: RES MF 10.0K 1/16W 1% AEC-Q200 0402; AGILE_PN: 470-75416; CAD_APPROVED: Yes; FPLIST: RC0402_25,RC0402_HD,0402_CC; HEIGHT: 0.4MM; MFG_NAME01: KOA SPEER; MFG_PN01: RK73H1ETTP1002F; PRIORITY_PN: 006-00552; ROHS: Yes; ROOM: 1V5_SB; Temp Range: –55 °C to +155 °C; Tolerance: 1%
R97 = RES: RES MF 255K 1/10W 1% AEC-Q200 0402; AGILE_PN: 470-31104; CAD_APPROVED: Yes; FPLIST: RC0402_25,RC0402_HD,0402_CC; HEIGHT: 0.40 MM; MFG_NAME01: KOA SPEER; MFG_PN01: RK73H1ETTP2553F; ROHS: Yes; Temp Range: -55C to +155C; Temp_Range: -55C to +155C; Tolerance: 1%; VOLTAGE: 50V
R98 R99 R103 = RES: RES MF ZERO OHM 1/10W -- 0402; AGILE_PN: 470-79965; CAD_APPROVED: Yes; FPLIST: RC0402_25,RC0402_HD,RC0402_X2,0402_CC; HEIGHT: 0.4MM; MFG_NAME01: PANASONIC; MFG_PN01: ERJ-2GE0R00X; ROHS: Yes; ROOM: VDD_GVDD_PS; TOL: 5%; Temp Range: –55 °C to +155 °C; VOLTAGE: 1/10W
R100 = RES: RES MF 6.65K 1/10W 1% AEC-Q200 0402; AGILE_PN: 470-82020; CAD_APPROVED: Yes; FPLIST: RC0402_25,RC0402_HD,0402_CC; HEIGHT: 0.4 MM; MFG_NAME01: KOA SPEER; MFG_PN01: RK73H1ETTP6651F; ROHS: Yes; Temp Range: -55C to +155C; Tolerance: 1%
R104 = RES: RES MF 49.9K 1/16W 1% 0402; AGILE_PN: 470-76043; CAD_APPROVED: Yes; FPLIST: RC0402_25,RC0402_HD,0402_CC; HEIGHT: 0.4MM; MFG_NAME01: BOURNS; MFG_PN01: CR0402-FX-4992GLF; ROHS: Yes; ROOM: PS_VDD_GVDD; Tolerance: 1%
R5731 = RES: RES MF 20K 1/16W 1% AEC-Q200 0402; AGILE_PN: 470-80743; CAD_APPROVED: Yes; FPLIST: RC0402_25,RC0402_HD,0402_CC; HEIGHT: 0.4MM; MFG_NAME01: KOA SPEER; MFG_PN01: RK73H1ETTP2002F; ROHS: Yes
TP215-TP219 TP286 = T_POINT_TH: TEST POINT PAD 20 MILS SMT, NOT PART TO ORDER; AGILE_PN: 211-81036; CAD_APPROVED: Yes; FPLIST: tpad_020_top,tpad_020_btm_nsp; HEIGHT: 0.127MM; MFG_NAME01: NO PART ORDER; MFG_PN01: NA; ROHS: Yes
U1 U23 U25 = AP62600SJ: IC VREG SYNC BUCK 0.6-7V 6A 4.5-18V QFN12; 3D_Mechanical_Footprint_File: http://fcl.am.freescale.net/ALLEGRO/step/qfn12_0p5_2p05x3p05mm.STEP; AGILE_PN: 315-84036; CAD_APPROVED: Yes; HEIGHT: 0.85 MM; MFG_NAME01: DIODES INC; Package Size: 2x3; ROHS: Yes; Supply Voltage: 4.5-18V
U631 = LTC7150_BGA42: IC VREG SYNC STEP-DOWN 0.6-5.5V 20A 3.1-20V BGA42; 3D_Mechanical_Footprint_File: http://fcl.am.freescale.net/ALLEGRO/step/bga42_0p8_5x6.STEP; AGILE_PN: 315-81406; CAD_APPROVED: Yes; HEIGHT: 1.5MM; MFG_NAME01: LINEAR TECHNOLOGY; MFG_PN01: LTC7150SEY#PBF; ROHS: Yes; Temp Range: -40C to 125C; Temp_Range: -40C to 125C; VOLTAGE: 3.1-20V
FB101 = BEAD_FERRITE: IND FER BEAD 120OHM@100MHZ 2A 25% 0603; AGILE_PN: 180-30008; CAD_APPROVED: Yes; FPLIST: IND_0603,0603_CC; HEIGHT: 0.95MM; MFG_NAME01: MURATA; MFG_PN01: BLM18PG121SH1; ROHS: Yes
R5737 R5894 = RES: RES MF 12.4K 1/10W 1% AEC-Q200 0402; AGILE_PN: 470-30957; CAD_APPROVED: Yes; FPLIST: RC0402_25,RC0402_HD,0402_CC; HEIGHT: 0.40 MM; MFG_NAME01: KOA SPEER; MFG_PN01: RK73H1ETTP1242F; ROHS: Yes; Temp Range: -55C to +155C; Tolerance: 1%
R5739 = RES: RES MF 17.4K 1/10W 1% AEC-Q200 0402; AGILE_PN: 470-30972; CAD_APPROVED: Yes; FPLIST: RC0402_25,RC0402_HD,0402_CC; HEIGHT: 0.40 MM; MFG_NAME01: KOA SPEER; MFG_PN01: RK73H1ETTP1742F; ROHS: Yes; Temp Range: -55C to +155C; Temp_Range: -55C to +155C; Tolerance: 1%; VOLTAGE: 50V
R5893 = RES: RES MF 9.88K 1/16W 0.5% 0402; AGILE_PN: 470-81390; CAD_APPROVED: Yes; FPLIST: RC0402_25,RC0402_HD,0402_CC; HEIGHT: 0.35MM; MFG_NAME01: YAGEO AMERICA; MFG_PN01: RT0402DRD079K88L; ROHS: Yes; Temp Range: -55&#8451; to 155&#8451;; Tolerance: 0.5%
BH9 = MOUNT_HOLE: MOUNTING HOLE DRILL 135 PAD 180 PLATED TH NO PART TO ORDER; AGILE_PN: 280-76617; CAD_APPROVED: Yes; HEIGHT: 0.1 MM; MFG_NAME01: NO PART TO ORDER; MFG_PN01: Mounting Hole - 135mil Drill PTH; ROHS: Yes; ROOM: VDD_GVDD_PS; SILK: VDD
BH10 = MOUNT_HOLE: MOUNTING HOLE DRILL 135 PAD 180 PLATED TH NO PART TO ORDER; AGILE_PN: 280-76617; CAD_APPROVED: Yes; HEIGHT: 0.1 MM; MFG_NAME01: NO PART TO ORDER; MFG_PN01: Mounting Hole - 135mil Drill PTH; ROHS: Yes; ROOM: VDD_GVDD_PS; SILK: GND
C85 C86 C93 C5260 C5273 C5274 C5285 C5343 C5344 = CAP_NP: CAP CER 1uF 10V 10% X7S 0402; AGILE_PN: 150-80357; CAD_APPROVED: Yes; FPLIST: CC0402_25,CC0402_HD,0402_CC,capc0402_l; HEIGHT: 0.6MM; MFG_NAME01: MURATA; MFG_PN01: GRM155C71A105KE11D; PRIORITY_PN: 021-00242; Package Size: 0402; ROHS: Yes; ROOM: VDD_GVDD_PS; Rated Voltage: 10V; SIGNAL_MODEL: DEFAULT_CAPACITOR_1e+06pF_2_1; TOL: 10%; Temp Range: -55C to +125C; Tolerance: 10%; VOLTAGE: 10V
C87 C94 C97 C124 C127 C2636 C2637 C5276 C5286 = CAP_NP: CAP CER 0.1uF 16V 10% X7R AEC-Q200 0402; AGILE_PN: 150-79025; CAD_APPROVED: Yes; FPLIST: CC0402_25,CC0402_HD,0402_CC,capc0402_l; HEIGHT: 0.55MM; MFG_NAME01: MURATA; MFG_PN01: GCM155R71C104KA55D; PRIORITY_PN: 021-00389; Package Size: 0402; Package Type: ø180mm Reel PAPER; ROHS: Yes; ROOM: VDD_GVDD_PS; Rated Voltage: 16V; SIGNAL_MODEL: DEFAULT_CAPACITOR_100000pF_2_1; TOL: 10%; Temp Range: -55C to +125C; Tolerance: 10%; VOLTAGE: 35V
C91 C107 C5261-C5264 C5280 C5290 = CAP_NP: CAP CER 100uF 10V 20% X5R 1210; AGILE_PN: 150-78879; CAD_APPROVED: Yes; FPLIST: CC1210,1210_CC; HEIGHT: 2.8MM; MFG_NAME01: MURATA; MFG_PN01: GRM32ER61A107ME20L; Package Size: 1210; Package Type: 7" Tape; ROHS: Yes; ROOM: XVDD_SVDD_PS; Rated Voltage: 10V; Temp Range: -55C to +85C; Tolerance: 20%; VOLTAGE: 16V
C92 C114 C5291 = CAP_NP: CAP CER 2.2uF 6.3V 10% X5R 0402; AGILE_PN: 150-79454; CAD_APPROVED: Yes; FPLIST: CC0402_25,CC0402_HD,0402_CC,capc0402_l; HEIGHT: 0.55MM; MFG_NAME01: MURATA; MFG_PN01: GRM155R60J225KE01D; PRIORITY_PN: 021-00281; ROHS: Yes; ROOM: FPGA; Rated Voltage: 6.3V; SIGNAL_MODEL: DEFAULT_CAPACITOR_2.2e+06pF_2_1; TOL: 20%; Temp Range: -55C to +85C; Tolerance: 10%; VOLTAGE: 6.3V
C98 C131 C5266 C5284 = CAP_NP: CAP CER 22uF 25V 20% X5R 0805; AGILE_PN: 150-79304; CAD_APPROVED: Yes; FPLIST: CC0805_OV,CC0805,0805_CC; HEIGHT: 1.45MM; MFG_NAME01: MURATA; MFG_PN01: GRM21BR61E226ME44; PRIORITY_PN: 021-00377; Package Size: 0805; Package Type: SMD; ROHS: Yes; ROOM: VDD_GVDD_PS; Rated Voltage: 25V; Temp Range: -55C to +85C; Tolerance: 20%; VOLTAGE: 25V
C99 C5275 = CAP_NP: CAP CER 0.22uF 10V 10% X7R AEC-Q200 0402; 3D_Mechanical_Footprint_File: http://fcl.am.freescale.net/ALLEGRO/step/cc0402_25.STEP; AGILE_PN: 150-79031; CAD_APPROVED: Yes; FPLIST: CC0402_25,CC0402_HD,0402_CC,capc0402_l; HEIGHT: 0.55MM; MFG_NAME01: MURATA; MFG_PN01: GRT155R71A224KE01D; ROHS: Yes; ROOM: VDD_GVDD_PS; Rated Voltage: 10V; SIGNAL_MODEL: CAP_NP_CC0402_25_DISCRETE_0.5_3_0.22uF; Temp Range: -55C to +125C; Tolerance: 10%; VOLTAGE: 16V
C101 C5269 = CAP_NP: CAP CER 0.01UF 50V 10% X7R 0402; AGILE_PN: 150-30114; CAD_APPROVED: Yes; FPLIST: CC0402_25,CC0402_HD,0402_CC,capc0402_l; HEIGHT: 0.55 MM; MFG_NAME01: MURATA; MFG_PN01: GRM155R71H103KA88D; PRIORITY_PN: 021-00302; ROHS: Yes; ROOM: VDD_GVDD_PS; Rated Voltage: 50V; SIGNAL_MODEL: DEFAULT_CAPACITOR_10000pF_2_1; TOL: 10%; Temp Range: -55C to +125C; Tolerance: 10%; VOLTAGE: 50V
C109 C110 = CAP_NP: CAP CER 0.01UF 50V 10% X7R 0402; AGILE_PN: 150-30114; CAD_APPROVED: Yes; FPLIST: CC0402_25,CC0402_HD,0402_CC,capc0402_l; HEIGHT: 0.55 MM; MFG_NAME01: MURATA; MFG_PN01: GRM155R71H103KA88D; PRIORITY_PN: 021-00302; ROHS: Yes; ROOM: PEX_SLOTS123_REFCLK; Rated Voltage: 50V; SIGNAL_MODEL: DEFAULT_CAPACITOR_10000pF_2_1; TOL: 10%; Temp Range: -55C to +125C; Tolerance: 10%; VOLTAGE: 50V
C115 C116 = CAP_NP: CAP CER 56PF 50V 5% C0G 0402; AGILE_PN: 150-30269; CAD_APPROVED: Yes; FPLIST: CC0402_25,CC0402_HD,0402_CC,capc0402_l; HEIGHT: 0.55 MM; MFG_NAME01: VENKEL COMPANY; MFG_PN01: C0402C0G500-560JNE; ROHS: Yes; ROOM: VDD_GVDD_PS; Rated Voltage: 50V; Temp Range: -55C to +125C; Tolerance: 5%; VOLTAGE: 50V
C5270 = CAP_NP: CAP CER 10pF 50V 1% C0G AEC-Q200 0402; 3D_Mechanical_Footprint_File: http://fcl.am.freescale.net/ALLEGRO/step/cc0402_25.STEP; AGILE_PN: 150-81416; CAD_APPROVED: Yes; FPLIST: cc0402_25,cc0402_hd,0402_cc,capc0402_l; HEIGHT: 0.55MM; MFG_NAME01: MURATA; MFG_PN01: GCM1555C1H100FA16; Package Size: 0402; Package Type: SMD/SMT; ROHS: Yes; Rated Voltage: 50V; Temp Range: -55C to +125C; Tolerance: 1%; VOLTAGE: 50V
C5272 = CAP_NP: CAP CER 470pF 50V 5% C0G 0402; AGILE_PN: 150-30004; CAD_APPROVED: YES; FPLIST: CC0402_25,CC0402_HD,0402_CC; HEIGHT: 0.55MM; MFG_NAME01: MURATA; MFG_PN01: GRM1555C1H471JA01D; Package Size: 0402; ROHS: Yes; Rated Voltage: 50V; Temp Range: -55C to +125C; Tolerance: 5%; VOLTAGE: 50V
C5277 C5278 C5287 C5288 = CAP_NP: CAP CER 22UF 25V 20% X5R 1210; AGILE_PN: 150-77795; CAD_APPROVED: Yes; FPLIST: CC1210,1210_CC; HEIGHT: 2.8MM; MFG_NAME01: AVX; MFG_PN01: 12103D226MAT2A; PRIORITY_PN: 021-00315; Package Size: 1210; ROHS: Yes; ROOM: VDD_GVDD_PS; Rated Voltage: 25V; Temp Range: -55C to +85C; Tolerance: 20%; VOLTAGE: 25V
C5279 C5283 C5289 = CAP_POL: CAP ALEL 330uF 25V 20% -- RADIAL; AGILE_PN: 150-78978; CAD_APPROVED: Yes; ESR: 0.014 OHMS; HEIGHT: 13 MM; MFG_NAME01: PANASONIC; MFG_PN01: 25SEPF330M; ROHS: Yes; ROOM: VDD_GVDD_PS; Rated Voltage: 25V; Temp Range: -55C to +150C; Temp_Range: –55 °C to +105 °C; Tolerance: 20%; VOLTAGE: 25V
C5292 C5293 = CAP_NP: CAP CER 0.1uF 16V 10% X7R AEC-Q200 0402; AGILE_PN: 150-79025; CAD_APPROVED: Yes; FPLIST: CC0402_25,CC0402_HD,0402_CC,capc0402_l; HEIGHT: 0.55MM; MFG_NAME01: MURATA; MFG_PN01: GCM155R71C104KA55D; PRIORITY_PN: 021-00389; Package Size: 0402; Package Type: ø180mm Reel PAPER; ROHS: Yes; ROOM: PEX_SLOTS123_REFCLK; Rated Voltage: 16V; SIGNAL_MODEL: DEFAULT_CAPACITOR_100000pF_2_1; TOL: 10%; Temp Range: -55C to +125C; Tolerance: 10%; VOLTAGE: 35V
J106 = CON12_98414_PMBUS: CON 2X6 SHRD TH 2MM CTR 244H AU 122L; 3D_Mechanical_Footprint_File: http://fcl.am.freescale.net/ALLEGRO/step/con12_shrd_2mm_th_122l.STEP; AGILE_PN: 210-80051; CAD_APPROVED: Yes; HEIGHT: 6.2MM; MFG_NAME01: FCI; MFG_PN01: 98414-G08-12ULF; ROHS: Yes; ROOM: VDD_GVDD_PS; SILK: VDD_PROG; Temp Range: -40°C to +125°C
L3 = INDUCTOR: IND -- 1.5UH@100KHZ 9A 20% SMT; AGILE_PN: 180-75776; CAD_APPROVED: Yes; HEIGHT: 3MM; MFG_NAME01: VISHAY INTERTECHNOLOGY; MFG_PN01: IHLP2525CZER1R5M01; PART_TYPE: POWER; ROHS: Yes; ROOM: VDD_GVDD_PS; TOL: 20%; Tolerance: 20%
L4 L5 = ETQP6F_2P: IND PWR 175nH@100kHZ 61A 10% SMD; 3D_Mechanical_Footprint_File: http://fcl.am.freescale.net/ALLEGRO/step/ind2_10p4x8.STEP; AGILE_PN: 180-78362; CAD_APPROVED: Yes; HEIGHT: 7.5MM; MFG_NAME01: COOPER BUSSMANN; MFG_PN01: FP1007R3-R17-R; PART_TYPE: POWER; ROHS: Yes; ROOM: VDD_GVDD_PS; TOL: 10%; Temp Range: -40C to 125C; Temp_Range: -40C to 125C; Tolerance: 10%
Q1 Q2 = PNP: TRAN PNP GEN 0.2A 40V SOT23; AGILE_PN: 480-75192; CAD_APPROVED: Yes; HEIGHT: 1.3MM; MFG_NAME01: ON SEMICONDUCTOR; MFG_PN01: MMBT3906LT1G; ROHS: Yes; ROOM: VDD_GVDD_PS
R40 R41 R5811 R5812 = RES: RES MF 1.0K 1/16W 1% 0402; AGILE_PN: 470-76037; CAD_APPROVED: Yes; FPLIST: RC0402_25,RC0402_HD,RC0402_X2,0402_CC; HEIGHT: 0.4MM; MFG_NAME01: YAGEO AMERICA; MFG_PN01: RC0402FR-071KL; PRIORITY_PN: 006-00553; ROHS: Yes; ROOM: VDD_GVDD_PS; SIGNAL_MODEL: DEFAULT_RESISTOR_1000OHM_2_1; TOL: 5%; Tolerance: 1%; VOLTAGE: 1/16W
R42 = RES: RES MF ZERO OHM 1/10W AEC-Q200 0603; AGILE_PN: 470-82905; ASSY_OPT: DNP; CAD_APPROVED: Yes; FPLIST: RC0603_OV,RC0603,0603_CC; HEIGHT: 0.55 MM; MFG_NAME01: YAGEO AMERICA; MFG_PN01: AC0603FR-070RL; ROHS: Yes; ROOM: VDD_GVDD_PS; Temp Range: -55 °C to +155 °C; VOLTAGE: 1/10W
R46 R53 R54 = RES: RES MF 49.9 OHM 1/10W 1% AEC-Q200 0402; AGILE_PN: 470-82539; CAD_APPROVED: YES; FPLIST: RC0402_25,RC0402_HD,0402_CC,RC0402_X2; HEIGHT: 0.4 MM; MFG_NAME01: PANASONIC; MFG_PN01: ERJ-2RKF49R9X; PRIORITY_PN: 006-00561; Package Size: 0402 (1005 Metric); ROHS: YES; ROOM: VDD_GVDD_PS; SIGNAL_MODEL: DEFAULT_RESISTOR_49.9OHM_2_1; TOL: 1%; Temp Range: -55°C to 155°C; Tolerance: 1%
R47-R49 = RES: RES MF 4.99K 1/16W 1% 0402; AGILE_PN: 470-76183; CAD_APPROVED: Yes; FPLIST: RC0402_25,RC0402_HD,0402_CC; HEIGHT: 0.4 MM; MFG_NAME01: SMEC; MFG_PN01: RC73A2Z4991FTF; ROHS: Yes; ROOM: VDD_GVDD_PS; Tolerance: 1%; VOLTAGE: 50V
R50 R61-R64 R78 = RES: RES MF 24.9K 1/16W 1% AEC-Q200 0402; AGILE_PN: 470-80726; CAD_APPROVED: Yes; FPLIST: RC0402_25,RC0402_HD,0402_CC; HEIGHT: 0.4MM; MFG_NAME01: VISHAY INTERTECHNOLOGY; MFG_PN01: CRCW040224K9FKED; ROHS: Yes; ROOM: VDD_GVDD_PS; Tolerance: 1%
R55 = RES: RES MF 68.1K  1/16W 1% 0402; AGILE_PN: 470-31043; CAD_APPROVED: Yes; FPLIST: RC0402_25,RC0402_HD,0402_CC; HEIGHT: 0.40MM; MFG_NAME01: ROHM; MFG_PN01: MCR01MZPF6812; ROHS: Yes; Tolerance: 1%
R56 = RES: RES MF 2.05K  1/10W 1% AEC-Q200 0402; AGILE_PN: 470-30868; CAD_APPROVED: Yes; FPLIST: RC0402_25,RC0402_HD,0402_CC; HEIGHT: 0.40 MM; MFG_NAME01: KOA SPEER; MFG_PN01: RK73H1ETTP2051F; ROHS: Yes; Temp Range: -55C to +155C; Temp_Range: -55C to +155C; Tolerance: 1%; VOLTAGE: 50V
R59 = RES: RES MF 10.0K 1/16W 1% AEC-Q200 0402; AGILE_PN: 470-75416; CAD_APPROVED: Yes; FPLIST: RC0402_25,RC0402_HD,0402_CC; HEIGHT: 0.4MM; MFG_NAME01: KOA SPEER; MFG_PN01: RK73H1ETTP1002F; PRIORITY_PN: 006-00552; ROHS: Yes; ROOM: ATX PS; Temp Range: –55 °C to +155 °C; Tolerance: 1%
R60 = RES: RES MF 24.9K 1/16W 1% AEC-Q200 0402; AGILE_PN: 470-80726; CAD_APPROVED: Yes; FPLIST: RC0402_25,RC0402_HD,0402_CC; HEIGHT: 0.4MM; MFG_NAME01: VISHAY INTERTECHNOLOGY; MFG_PN01: CRCW040224K9FKED; ROHS: Yes; ROOM: VDD_GVDD_PS; Temp_Range: -55C to +155C; Tolerance: 1%; VOLTAGE: 50V
R75 R5814 = RES: RES MF 2.67K 1/16W 1% 0402; AGILE_PN: 470-30880; CAD_APPROVED: Yes; FPLIST: RC0402_25,RC0402_HD,0402_CC; HEIGHT: 0.40 MM; MFG_NAME01: YAGEO AMERICA; MFG_PN01: RT0402FRE072K67L; ROHS: Yes; ROOM: VDD_GVDD_PS; Tolerance: 1%
R628 R629 = RES: RES MF 4.99K 1/16W 1% 0402; AGILE_PN: 470-76183; ASSY_OPT: DNP; CAD_APPROVED: Yes; FPLIST: RC0402_25,RC0402_HD,0402_CC; HEIGHT: 0.4 MM; MFG_NAME01: SMEC; MFG_PN01: RC73A2Z4991FTF; ROHS: Yes; ROOM: VDD_GVDD_PS; Tolerance: 1%; VOLTAGE: 50V
R5806 = RES: RES MF 4.32K  1/16W 1% 0402; AGILE_PN: 470-30906; CAD_APPROVED: Yes; FPLIST: RC0402_25,RC0402_HD,0402_CC; HEIGHT: 0.40 MM; MFG_NAME01: VISHAY INTERTECHNOLOGY; MFG_PN01: CRCW04024K32FKED; ROHS: Yes; ROOM: VDD_GVDD_PS; Tolerance: 1%
R5807 R5809 = RES: RES MF 7.32K  1/10W 1% AEC-Q200 0402; AGILE_PN: 470-30932; CAD_APPROVED: Yes; FPLIST: RC0402_25,RC0402_HD,0402_CC; HEIGHT: 0.40 MM; MFG_NAME01: KOA SPEER; MFG_PN01: RK73H1ETTP7321F; ROHS: Yes; ROOM: VDD_GVDD_PS; Temp Range: -55°C to +155°C; Temp_Range: -55°C to +155°C; Tolerance: 1%
R5808 = RES: RES MF 9.09K 1/10W 1% AEC-Q200 0402; AGILE_PN: 470-81679; CAD_APPROVED: Yes; FPLIST: RC0402_25,RC0402_HD,0402_CC; HEIGHT: 0.40 MM; MFG_NAME01: KOA SPEER; MFG_PN01: RK73H1ETTP9091F; ROHS: Yes; ROOM: VDD_GVDD_PS; Temp Range: -55C to +155C; Temp_Range: -55C to +155C; Tolerance: 1%; VOLTAGE: 50V
R5810 = RES: RES TF 11.3K 1/16W 0.5% 0402; AGILE_PN: 470-76301; CAD_APPROVED: Yes; FPLIST: RC0402_25,RC0402_HD,0402_CC; HEIGHT: 0.4 MM; MFG_NAME01: SUSUMU CO. LTD.; MFG_PN01: RR0510P-1132-DC; ROHS: Yes; ROOM: VDD_GVDD_PS; Tolerance: 0.5%
R5813 = RES: RES MF ZERO OHM 1/10W AEC-Q200 0603; AGILE_PN: 470-82905; CAD_APPROVED: Yes; FPLIST: RC0603_OV,RC0603,0603_CC; HEIGHT: 0.55 MM; MFG_NAME01: YAGEO AMERICA; MFG_PN01: AC0603FR-070RL; ROHS: Yes; ROOM: VDD_GVDD_PS; Temp Range: -55 °C to +155 °C; VOLTAGE: 1/10W
U3 = LTC3882_40P_EP: IC CONTROLLER DCDC DUAL OUT 0.5-5.25V -- 4.5-13.8V QFN40; 3D_Mechanical_Footprint_File: http://fcl.am.freescale.net/ALLEGRO/step/qfn40_0p5_6p1x6p1.STEP; AGILE_PN: 315-80652; CAD_APPROVED: Yes; HEIGHT: 0.8MM; MFG_NAME01: LINEAR TECHNOLOGY; MFG_PN01: LTC3882EUJ#PBF; ROHS: Yes; ROOM: VDD_GVDD_PS; VOLTAGE: 3V-13.2V
U7 U9 = SIC620ACD_MLP55: IC HALF-BRIDGE POWER MODULE 4.5-18V 3.3V-PWM 60A PPAK; AGILE_PN: 315-84265; CAD_APPROVED: Yes; HEIGHT: 0.8MM; MFG_NAME01: VISHAY INTERTECHNOLOGY; Package Size: PowerPAK® MLP55-31L; ROHS: Yes; Supply Voltage: 4.5V ~ 18V; Temp Range: -40°C to 125°C; VOLTAGE: 3.3V

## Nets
12V0_2_VDD_FLT: C5276.1 C5277.1 C5278.1 C5279.1 C5286.1 C5287.1 C5288.1 C5289.1 L3.1 R43.2 U7.8(VIN_1) U7.34(VIN_2) U9.8(VIN_1) U9.34(VIN_2)
12V0_FILTERED_PS_GVDD: C2679.1 C2680.1 C5122.1 C5125.1 C5126.1 FL6.3(OUTPUT) R92.1 U631.C2(PVIN1) U631.C5(PVIN2) U631.C6(PVIN3) U631.D1(PVIN4) U631.D2(PVIN5) U631.D5(PVIN6) U631.D6(PVIN7)
GND: BH10.1 C1.1 C3.2 C4.2 C5.1 C6.2 C8.2 C10.2 C83.2 C84.2 C85.2 C89.1 C91.2 C94.2 C97.2 C98.2 C105.2 C107.2 C109.2 C110.2 C114.2 C125.1 C127.2 C131.2 C1240.1 C1241.2 C1242.2 C1243.2 C1247.1 C1250.1 C1251.2 C1252.2 C1253.2 C1254.2 C1256.2 C1257.1 C2636.2 C2637.2 C2673.2 C2679.2 C2680.2 C5122.2 C5123.2 C5124.2 C5125.2 C5126.2 C5127.2 C5128.2 C5129.2 C5130.2 C5134.2 C5138.2 C5139.1 C5140.2 C5141.1 C5142.2 C5143.1 C5144.2 C5145.2 C5146.2 C5147.2 C5148.2 C5150.1 C5151.2 C5152.2 C5153.1 C5154.2 C5155.2 C5156.2 C5157.1 C5158.2 C5160.1 C5161.2 C5162.2 C5163.1 C5164.2 C5165.2 C5166.2 C5167.1 C5168.2 C5259.2 C5260.2 C5261.2 C5262.2 C5263.2 C5264.2 C5265.2 C5266.2 C5267.2 C5268.2 C5273.2 C5274.2 C5276.2 C5277.2 C5278.2 C5279.2 C5280.2 C5281.2 C5282.2 C5283.2 C5284.2 C5285.2 C5286.2 C5287.2 C5288.2 C5289.2 C5290.2 C5291.2 C5292.2 C5293.2 C5343.2 C5344.2 FL6.2A(GND) FL6.2B(GND) J106.3(GND1) J106.10(GND2) R46.2 R50.2 R54.2 R78.2 R102.2 R103.2 R5731.2 R5739.2 R5813.2 R5893.2 U1.1(PGND) U1.11(GND) U7.4(CGND_1) U7.28(PGND_2) U7.32(CGND_2) U7.35(PGND_1) U9.4(CGND_1) U9.28(PGND_2) U9.32(CGND_2) U9.35(PGND_1) U14.3(GND) U14.9(EPAD) U17.3(GND) U17.9(EPAD) U23.1(PGND) U23.11(GND) U25.1(PGND) U25.11(GND) U631.E1(PGND1) U631.E2(PGND2) U631.E5(PGND3) U631.E6(PGND4) U631.F1(PGND5) U631.F2(PGND6) U631.F5(PGND7) U631.F6(PGND8) U631.G1(PGND9) U631.G2(PGND10) U631.G5(PGND11) U631.G6(PGND12) ; also on sheet 6 7 8 9 10 15 16 18 19 20 21 22 24 25 27 28 29 30 31 32 33 34 35 36 37 38 39 40 41 42 43 44 45 46 47 48 49 50 51 52 53 54
SVDD: C5154.1 C5155.1 C5156.1 C5157.2 FB101.1 L54.2 R5737.2 ; also on sheet 19
VCC_3.3: C84.1 C92.1 C93.1 C105.1 C1240.2 C1250.2 C5260.1 R42.1 R47.1 R48.1 R49.1 R58.1 R628.1 R629.1 U3.25(VDD33) U3.26(VCC) U14.5(VDRV) U17.5(VDRV) ; also on sheet 6 16 18 24 25 31 32 33 36 39 40 41 42 43 44 47 48 49 50 51 53
VCC_5: C85.1 C5266.1 C5273.1 C5274.1 C5284.1 C5285.1 C5343.1 C5344.1 R40.1 R41.1 R5811.1 R5812.1 U7.3(VCIN) U7.29(VDRV) U9.3(VCIN) U9.29(VDRV) ; also on sheet 6 49
VCC_12: C3.1 C4.1 C5.2 C5151.1 C5152.1 C5153.2 C5161.1 C5162.1 C5163.2 FL6.1(INPUT) U1.2(VIN) U23.2(VIN) U25.2(VIN) ; also on sheet 6 15 47 48 53
VCC_12_8P: C5283.1 L3.2 ; also on sheet 6
VDD: BH9.1 C91.1 C98.1 C107.1 C109.1 C110.1 C114.1 C131.1 C2636.1 C2637.1 C5261.1 C5262.1 C5263.1 C5264.1 C5265.1 C5267.1 C5268.1 C5280.1 C5281.1 C5282.1 C5290.1 C5291.1 C5292.1 C5293.1 L4.1 L5.1 R46.1 R52.1 R53.1 R76.1 ; also on sheet 18 20
VDD_2V5_AUX: C86.1 R60.1 R61.1 R62.1 R63.1 R64.1 U3.22(VDD25)
VDD_ALERT_B: R49.2 U3.11(~{ALERT}) ; also on sheet 8
VDD_ASEL0: R60.2 R5806.1 U3.16(ASEL0)
VDD_ASEL1: R61.2 R5808.1 U3.17(ASEL1)
VDD_COMP0: C5270.1 R55.1 R57.1 U3.1(COMP0)
VDD_COMP1: R57.2 U3.29(COMP1)
VDD_FB0: C5270.2 C5271.2 C5272.1 U3.40(FB0)
VDD_FB1: R58.2 U3.30(FB1)
VDD_FREQ_CFG: R63.2 R5809.1 U3.20(FREQ_CFG)
VDD_IAVG0: C115.1 R66.2 U3.39(IAVG0)
VDD_IAVG1: C116.1 R66.1 U3.31(IAVG1)
VDD_ISENSE0+: C99.2 R5814.2 U3.38(ISENSE0+)
VDD_ISENSE0-: C99.1 R52.2 U3.37(ISENSE0-)
VDD_ISENSE1+: C5275.2 R75.2 U3.32(ISENSE1+)
VDD_ISENSE1-: C5275.1 R76.2 U3.33(ISENSE1-)
VDD_PH1_FLT: L4.2 R5814.1 U9.16(VSWH_1) U9.26(VSWH_2)
VDD_PH2_FLT: L5.2 R75.1 U7.16(VSWH_1) U7.26(VSWH_2)
VDD_PHAS_CFG: R64.2 R5810.1 U3.21(PHAS_CFG)
VDD_PWM0: U3.7(TG0/PWM0) U9.1(PWM)
VDD_PWM1: U3.27(TG1/PWM1) U7.1(PWM)
VDD_SCL: J106.4(SCL) R627.1 R628.2 U3.9(SCL)
VDD_SDA: J106.2(SDA) R629.2 R630.1 U3.10(SDA)
VDD_SENSE0+: R53.2 R56.2 R65.1 R631.2 U3.36(VSENSE0+)
VDD_SENSE0-: R54.1 R632.2 U3.35(VSENSE0-)
VDD_SENSE_N: R632.1 ; also on sheet 18
VDD_SENSE_P: R631.1 ; also on sheet 18
VDD_SGND: C86.2 C92.2 C93.2 C101.1 C115.2 C116.2 C5269.1 Q1.1(B) Q1.3(C) Q2.1(B) Q2.3(C) R59.2 R5806.2 R5807.2 R5808.2 R5809.2 R5810.2 R5813.1 U3.5(IAVG_GND) U3.41(GND_(VSENSE1-))
VDD_SH_CLK: R48.2 U3.24(SHARE_CLK)
VDD_SH_SYNC: R47.2 U3.8(SYNC)
VDD_SH_WP: R59.1 U3.23(WP)
VDD_TMON0: C97.1 R50.1 U9.30(THWN)
VDD_TMON1: C127.1 R78.1 U7.30(THWN)
VDD_TSNS0: C101.2 Q1.2(E) U3.2(TSNS0)
VDD_TSNS1: C5269.2 Q2.2(E) U3.3(TSNS1)
VDD_VOUT_CFG: R62.2 R5807.1 U3.18(VOUT0_CFG) U3.19(VOUT1_CFG)
VDD_VSENSE1+: R65.2 U3.34(VSENSE1+)
GVDD: C2673.1 C5123.1 C5124.1 C5127.1 C5128.1 C5129.1 C5130.1 FB81.1 FB84.1 L7.2 R93.1 ; also on sheet 20 28 29 30 31 32 33
GVDD_FB: C5132.2 R96.2 R100.1 U631.A5(FB)
GVDD_FDIVH: C5132.1 R93.2 R96.1 R98.2
GVDD_FDIVL: R99.2 R100.2 R101.1 R102.1
GVDD_GND: C5131.2 C5133.2 C5135.2 C5136.2 C5137.2 R95.2 R97.2 R103.1 U631.B5(SGND)
GVDD_INTVCC: C5134.1 U631.B6(INTVCC)
GVDD_ITH: C5136.1 R104.1 U631.A4(ITH)
GVDD_ITHX: C5137.1 R104.2
GVDD_MS: R95.1 U631.B3(MODE/SYNC)
GVDD_RT: R97.1 U631.A3(RT)
GVDD_SENSE: R98.1 ; also on sheet 32
GVDD_SVIN: C5131.1 R92.2 U631.C1(SVIN)
GVDD_SW: L7.1 U631.C3(SW1) U631.C4(SW2) U631.D3(SW3) U631.D4(SW4) U631.E3(SW5) U631.E4(SW6) U631.F3(SW7) U631.F4(SW8) U631.G3(SW9) U631.G4(SW10)
GVDD_TRK: C5133.1 U631.B4(TRACK_SS)
GVDD_VOUTM: C5135.1 R101.2 U631.A6(VOUTM)
GVSS_SENSE: R99.1 ; also on sheet 32
I2C1_SCL: R627.2 ; also on sheet 8 24 31 32 33 50 51 53
I2C1_SDA: R630.2 ; also on sheet 8 24 31 32 33 50 51 53
M_VREF_A: C125.2 C1247.2 C1254.1 U17.8(VTTREF) ; also on sheet 28 29 31 32
M_VREF_B: C1252.1 C1256.1 C1257.2 FB86.2 ; also on sheet 30 33
M_VTT_A: C1241.1 C1242.1 C1243.1 C5144.1 C5145.1 C5146.1 U17.2(VTT) ; also on sheet 31 32
M_VTT_B: C1251.1 C1253.1 C5147.1 C5148.1 U14.2(VTT) ; also on sheet 33
OVDD: C6.1 C8.1 C5138.1 C5139.2 L1.2 R5730.2 ; also on sheet 10 18 20 21 24 25 27 34 35 36
PHY_1V0: FB101.2 ; also on sheet 42 43
PS_1V0_EN: TP218.1(TP) U23.3(EN) ; also on sheet 8
PS_1V0_PG: U23.6(PG) ; also on sheet 8
PS_GVDD_EN: TP215.1(TP) U631.B2(RUN) ; also on sheet 8
PS_GVDD_PG: TP216.1(TP) U631.A2(PGOOD) ; also on sheet 8
PS_OVDD_EN: TP217.1(TP) U1.3(EN) ; also on sheet 8
PS_OVDD_PG: U1.6(PG) ; also on sheet 8
PS_VDD_EN: U3.14(RUN0) U3.15(RUN1) ; also on sheet 8
PS_VDD_PG: U3.12(~{GPIO0}) U3.13(~{GPIO1}) ; also on sheet 8
PS_VTT_EN: U14.7(EN) U17.7(EN) ; also on sheet 8
PS_XVDD_EN: TP219.1(TP) U25.3(EN) ; also on sheet 8
PS_XVDD_PG: U25.6(PG) ; also on sheet 8
VTT_A_SENSE: R5734.1 ; also on sheet 32
VTT_B_SENSE: R5735.1 ; also on sheet 33
XVDD: C5164.1 C5165.1 C5166.1 C5167.2 L55.2 R5894.1 ; also on sheet 19 21
N16616368: C83.1 C89.2 C5259.1 FB86.1 U14.8(VTTREF)
N18838531: C94.1 R43.1 U3.4(VINSNS)
N18839314: C87.2 R44.2
N18839320: C87.1 U9.7(PHASE)
N18839399: C5271.1 R55.2
N18839410: C5272.2 R56.1
N18839524: R77.1 U7.5(BOOT)
N18839526: C124.2 R77.2
N18839532: C124.1 U7.7(PHASE)
N31714319: C1.2 U1.4(MODE) U1.9(VCC)
N31714350: C2.1 U1.7(BST)
N31714354: C2.2 R1.1
N31714416: L1.1 R1.2 U1.8(SW)
N31714501: R5730.1 R5731.1 U1.12(FB)
N31714572: C10.1 U1.10(SS/TR)
N31717308: C5140.1 FB81.2 R5788.1 U17.1(DDQ)
N31718323: C5142.1 FB84.2 R5789.1 U14.1(DDQ)
N31722569: C5141.2 R5788.2 U17.6(REF)
N31724252: C5143.2 R5789.2 U14.6(REF)
N31726596: R5734.2 U17.4(VTTSEN)
N31727679: R5735.2 U14.4(VTTSEN)
N31789752: C5150.2 U23.4(MODE) U23.9(VCC)
N31789783: C5149.1 U23.7(BST)
N31789787: C5149.2 R5736.1
N31789873: L54.1 R5736.2 U23.8(SW)
N31789971: R5737.1 R5739.1 U23.12(FB)
N31790039: C5158.1 U23.10(SS/TR)
N31884769: C5160.2 U25.4(MODE) U25.9(VCC)
N31884800: C5159.1 U25.7(BST)
N31884804: C5159.2 R5740.1
N31884868: L55.1 R5740.2 U25.8(SW)
N31884952: R5893.1 R5894.2 U25.12(FB)
N31885020: C5168.1 U25.10(SS/TR)
N33496283: R44.1 U9.5(BOOT)
N33510179: R40.2 U9.31(~{DSBL})
N33510235: R41.2 U9.2(~{ZCD_EN})
N33521269: R5812.2 U7.31(~{DSBL})
N33521274: R5811.2 U7.2(~{ZCD_EN})
N34055964: J106.1(AUXP) TP286.1(TP)
N34055974: J106.5(LGKPWR) R42.2

Not connected (* = marked no-connect by the designer): J106 6(ALERT_B)* 7(GPO_1)* 8(OUTEN)* 9(GPO_2)* 11(AUXSCL)* 12(AUXSDA)*; U1 5(FSEL)*; U3 6(BG0/EN0)* 28(BG1/EN1)*; U7 6(GH)* 27(GL); U9 6(GH)* 27(GL)*; U23 5(FSEL)*; U25 5(FSEL)*; U631 A1(PHMODE)* B1(CLKOUT)*

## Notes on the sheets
sheet 11
- GVDD & OVDD POWER
- GVDD: 1.50V
               ±3%
               20A
- Rx
- Place near regulator
- Rt
- Analog diff pair
- (>1.2V)
- Ry
- Place near regulator
- LTC7150 CONFIGURATION
  * VOUT
       VOUT = 0.6 * [1+(Rx/Ry)]
       VOUT = 0.6 * [1+(10_000 / 6_650)]
       VOUT = 1.5V
  * RT(FREQUENCY)
       FSW = 1.67E11 / RT
       FSW = 633 kHz
  * TRACK/SS
      Soft-start: formula TBD
  * MODE/SYNC
      GND   = discontinuous
      FLOAT = forced continuous
  * PHMODE
      FLOAT = 2phase (internal)
  * ITH (LOOP COMPENSATION)
      See spec.
- OVDD:  1.80V
               ±3%
               6A (max)
- (>1.2V)
- CONFIG
  ========================
  MODE = VCC (Forced PWM)
  FSEL = OPEN (800kHz)
- NOTE: Could be replaced with AP64501 @ 5A
  (sufficient) which is qual'd for -40-125C
sheet 12
- VDD POWER
- VDD: 1.05V  (T4240A)
            +/-3%
            @70A
- PLACE CLOSE
  (thermo-coupled)
- PLACE CLOSE
  (thermo-coupled)
- ADDR = 0x63
- FREQ = 450KHZ
- VOUT0,VOUT1 = 1.05V
- PHASE0 = 0
  PHASE1 = 180
- NVM/PMBus programmed
  to 1.025V or per VID fuses
sheet 13
- DDR VTT+MVREF POWER
- max 2A
- Place close to LDO
- Place close to DDR3 DIMMs #1&2
- VREF_A
  0.75V @ 0.02A
- 25mil
- VTT_A
  0.75V @ 2A
- Place close to LDO
- Place close to DDR3 DIMM #3
- VREF_B
  0.75V @ 0.02A
- max 2A
- 25mil
- 25mil
- VTT_B
  0.75V @ 2A
sheet 14
- SVDD & XVDD POWER
- SVDD:  1.00V
               ±3%
               6A (max)
- Rx
- (>1.2V)
- Ry
- CONFIG
  ========================
  MODE = VCC (Forced PWM)
  FSEL = OPEN (800kHz)
  VOUT = 0.6*(Rx/Ry+1)
       = 1.02 V
- XVDD:  1.35V
               ±3%
               6A (max)
- Rx
- (>1.2V)
- Ry
- CONFIG
  ========================
  MODE = VCC (Forced PWM)
  FSEL = OPEN (800kHz)
  VOUT = 0.6*(Rx/Ry+1)
       = 1.50 V
- NOTE: To change XVDD to 1.50V
  Rx = 14.7K 12.4K
  Ry = 9.76K 9.88K
